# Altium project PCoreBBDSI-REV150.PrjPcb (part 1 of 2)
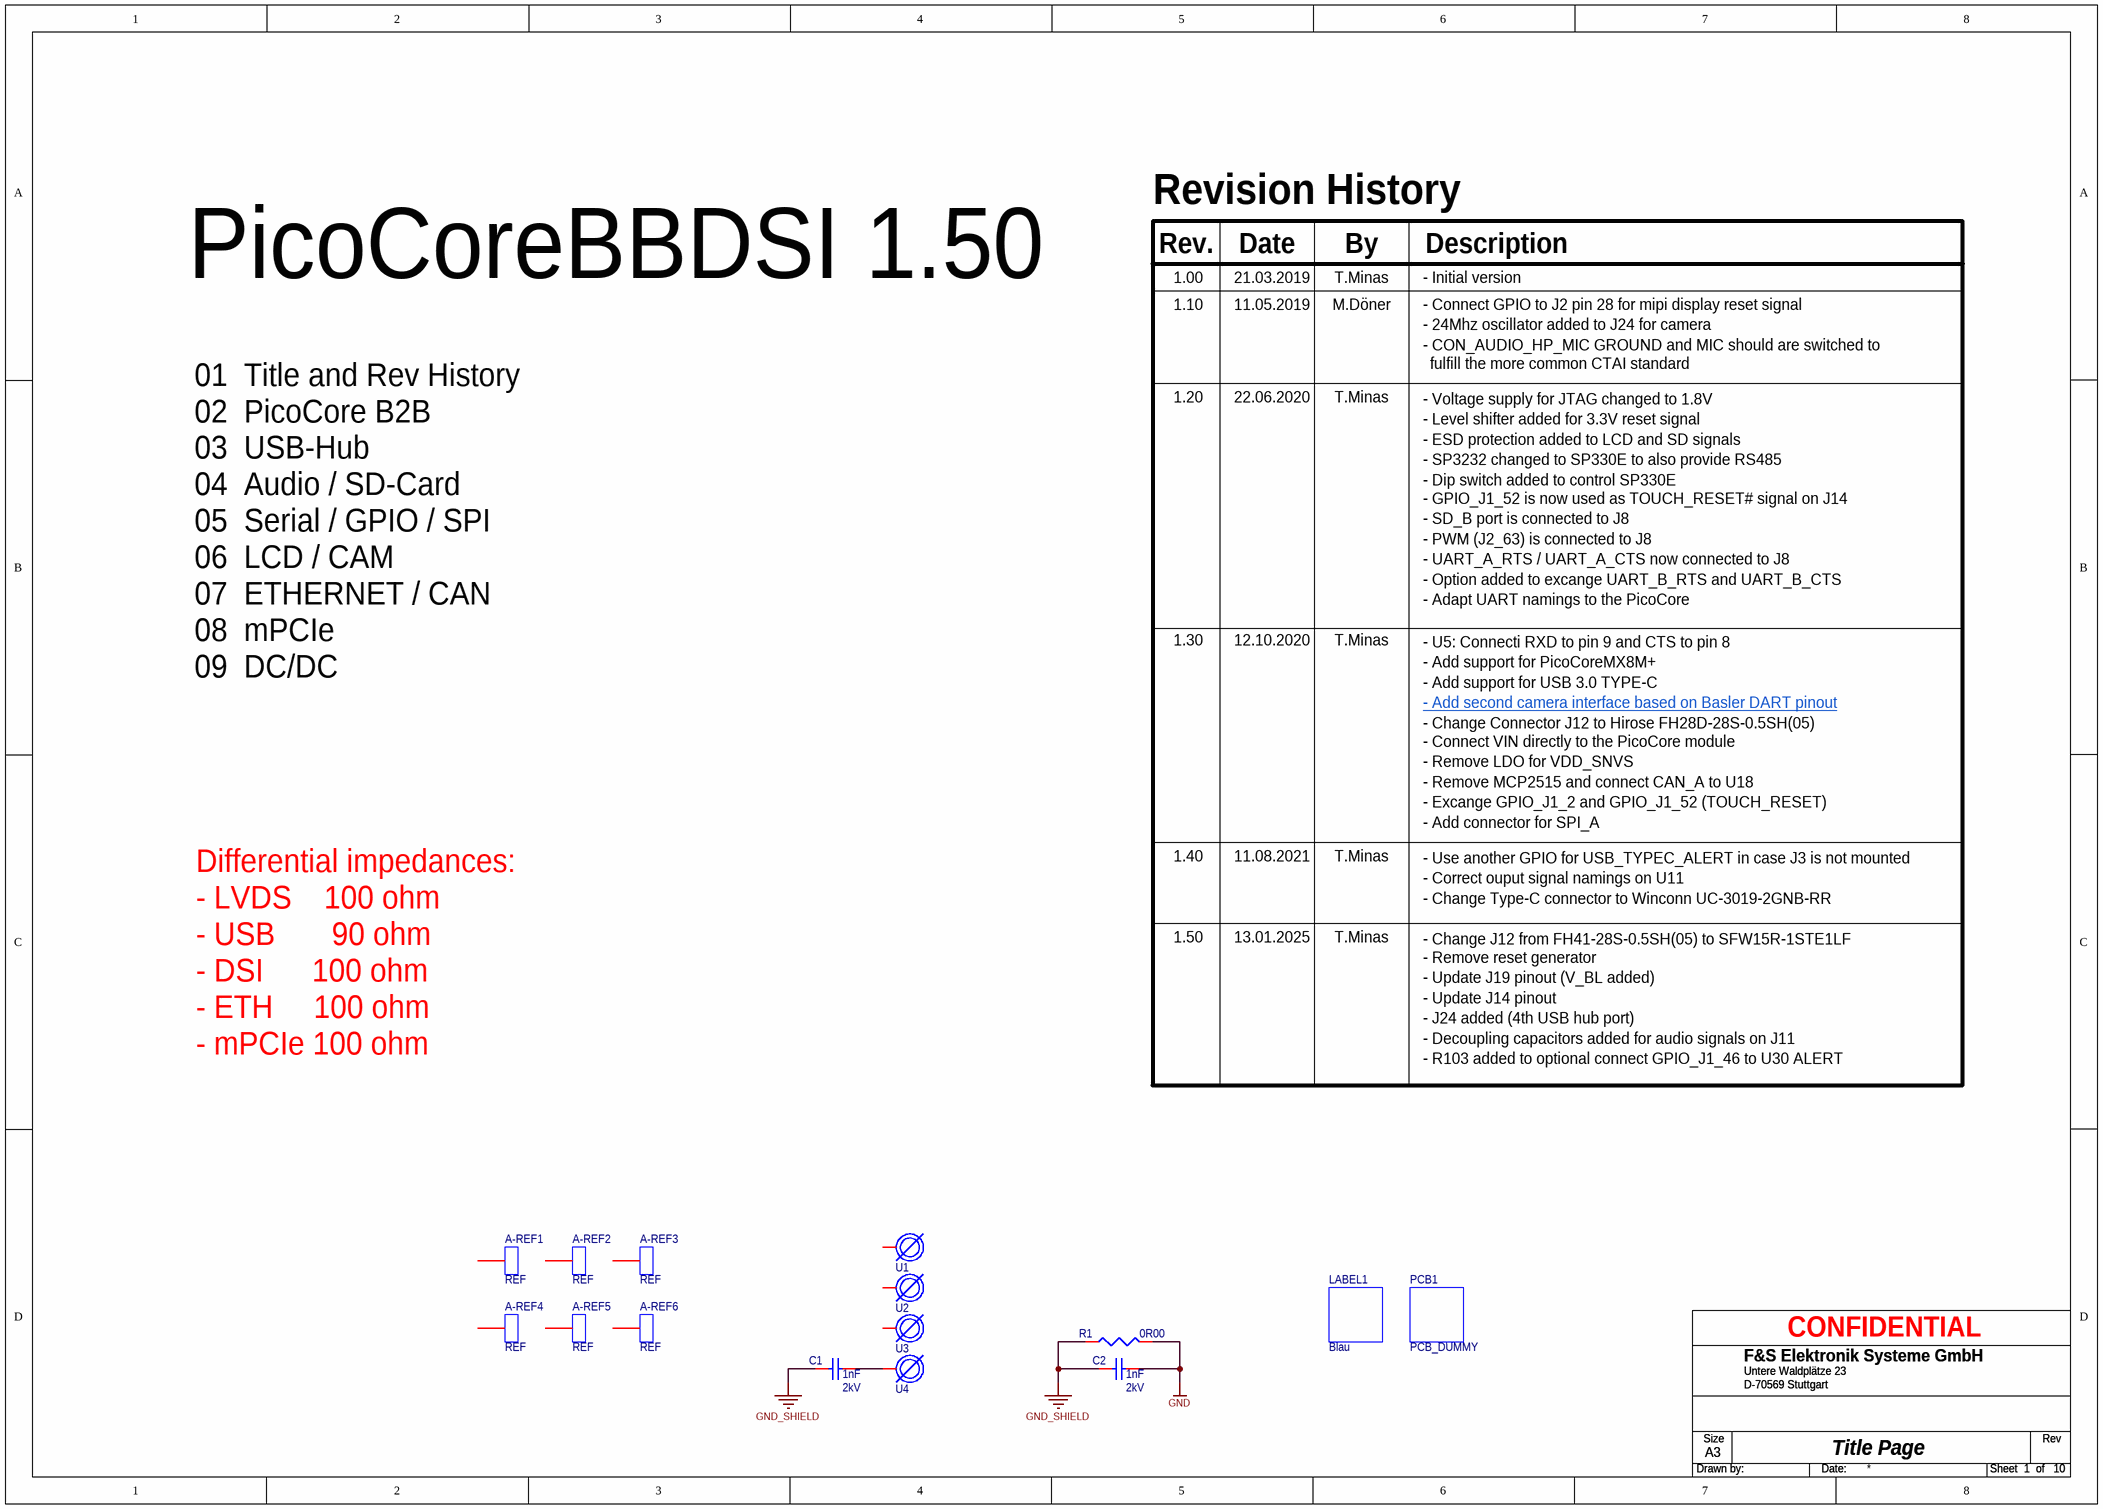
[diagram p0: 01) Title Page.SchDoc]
MA: T.Minas; projectTitle: PicoCoreBBDSI; rev: 1.50
10 sheets, 358 parts. Net scope: flat (ports and power ports of the same name join across sheets).
Board files: PCoreBBDSI-REV150.PcbDoc, PCoreBBDSI-REV150_Panel.PcbDoc
Sheets:
  01) Title Page.SchDoc
  02) PicoCore B2B.SchDoc
  03) USB-HUB.SchDoc
  04) USB AUDIO SD.SchDoc
  05) USB3.0 Type-C.SchDoc
  06) Serial GPIO.SchDoc
  07) LCD CAM.SchDoc
  08) Ethernet Can.SchDoc
  09) mPCIe.SchDoc
  10) DCDC.SchDoc

## Sheet 01) Title Page.SchDoc: Title Page
size A3; Origin: Eagle; DrawnBy: T.Minas; DocumentNumber: 1; Revision: 1.50; SheetNumber: 1; SheetTotal: 10; Project: PicoCoreBBDSI

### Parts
A-REF1  REF  [Fiducial]  (no BOM)
A-REF2  REF  [Fiducial]  (no BOM)
A-REF3  REF  [Fiducial]  (no BOM)
A-REF4  REF  [Fiducial]  (no BOM)
A-REF5  REF  [Fiducial]  (no BOM)
A-REF6  REF  [Fiducial]  (no BOM)
C1  1nF  Voltage: 2kV  [C1206]
C2  1nF  Voltage: 2kV  [C1206]
LABEL1  Blau
PCB1  PCB_DUMMY
R1  0R00  [R0805]
U1  MOUNT_HOLE  [HOLE-3.2x6]  (value not drawn)  (no BOM)
U2  MOUNT_HOLE  [HOLE-3.2x6]  (value not drawn)  (no BOM)
U3  MOUNT_HOLE  [HOLE-3.2x6]  (value not drawn)  (no BOM)
U4  MOUNT_HOLE  [HOLE-3.2x6]  (value not drawn)  (no BOM)

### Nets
GND: C2.2 R1.2
GND_SHIELD: C1.1 C2.1 R1.1
NetC1_2: C1.2 U4.1

Not connected (* = marked no-connect by the designer): A-REF1 1; A-REF2 1; A-REF3 1; A-REF4 1; A-REF5 1; A-REF6 1; U1 1; U2 1; U3 1

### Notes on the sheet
- Revision History
- Rev.
- Date
- By
- Description
- PicoCoreBBDSI 1.50
- 1.00
- 1.10
- 21.03.2019
- 11.05.2019
- T.Minas
- M.Döner
- - Initial version
- - Connect GPIO to J2 pin 28 for mipi display reset signal
- - 24Mhz oscillator added to J24 for camera
- - CON_AUDIO_HP_MIC GROUND and MIC should are switched to
- fulfill the more common CTAI standard
- 1.20
- 22.06.2020
- - Voltage supply for JTAG changed to 1.8V
- - Level shifter added for 3.3V reset signal
- - ESD protection added to LCD and SD signals
- - SP3232 changed to SP330E to also provide RS485
- - Dip switch added to control SP330E
- - GPIO_J1_52 is now used as TOUCH_RESET# signal on J14
- - SD_B port is connected to J8
- - PWM (J2_63) is connected to J8
- - UART_A_RTS / UART_A_CTS now connected to J8
- - Option added to excange UART_B_RTS and UART_B_CTS
- 1.30
- 12.10.2020
- - Adapt UART namings to the PicoCore
- - U5: Connecti RXD to pin 9 and CTS to pin 8
- 01  Title and Rev History
  02  PicoCore B2B
  03  USB-Hub
  04  Audio / SD-Card
  05  Serial / GPIO / SPI
  06  LCD / CAM
  07  ETHERNET / CAN
  08  mPCIe
  09  DC/DC
- - Add support for PicoCoreMX8M+
- - Add support for USB 3.0 TYPE-C
- - Add second camera interface based on Basler DART pinout <https://www.baslerweb.com/en/products/cameras/area-scan-cameras/dart/daa3840-30mc-s-mount/#tab=accessories>
- - Change Connector J12 to Hirose FH28D-28S-0.5SH(05)
- - Connect VIN directly to the PicoCore module
- - Remove LDO for VDD_SNVS
- - Remove MCP2515 and connect CAN_A to U18
- 1.40
- 11.08.2021
- - Excange GPIO_J1_2 and GPIO_J1_52 (TOUCH_RESET)
- - Add connector for SPI_A
- - Use another GPIO for USB_TYPEC_ALERT in case J3 is not mounted
- - Correct ouput signal namings on U11
- - Change Type-C connector to Winconn UC-3019-2GNB-RR
- 1.50
- 13.01.2025
- - Change J12 from FH41-28S-0.5SH(05) to SFW15R-1STE1LF
- - Remove reset generator
- - Update J19 pinout (V_BL added)
- - Update J14 pinout
- Differential impedances:
  - LVDS    100 ohm
  - USB       90 ohm
  - DSI      100 ohm
  - ETH     100 ohm
  - mPCIe 100 ohm
- - J24 added (4th USB hub port)
- - Decoupling capacitors added for audio signals on J11
- - R103 added to optional connect GPIO_J1_46 to U30 ALERT

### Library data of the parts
C1 C2 = 473: 1nF  10%  2kV  X7R  1206; FS-EDV-Nummer: B.CKV.89; Class: Capacitor Ceramic; Tolerance: 10; ID: 473
LABEL1 = 2752: F&S Seriennummer Label Blau; Part Number: MAC Blau; FS-EDV-Nummer: B.LAB.MACBLU; ID: 2752
PCB1 = PCB_DUMMY: FS-EDV-Nummer: B.MLP.PCBBDSI.15
R1 = 6: 0R00 0,125W max 5% SMD 0805; FS-EDV-Nummer: B.R000.2.S; Power: 0,125W; Tolerance: 5; ID: 6
U1-U4 = MOUNT_HOLE: CLASS: IC

## Sheet 02) PicoCore B2B.SchDoc: PicoCore B2B
size A3; Origin: Eagle; DrawnBy: T.Minas; DocumentNumber: 2; Revision: 1.50; SheetNumber: 2; SheetTotal: 10; Project: PicoCoreBBDSI
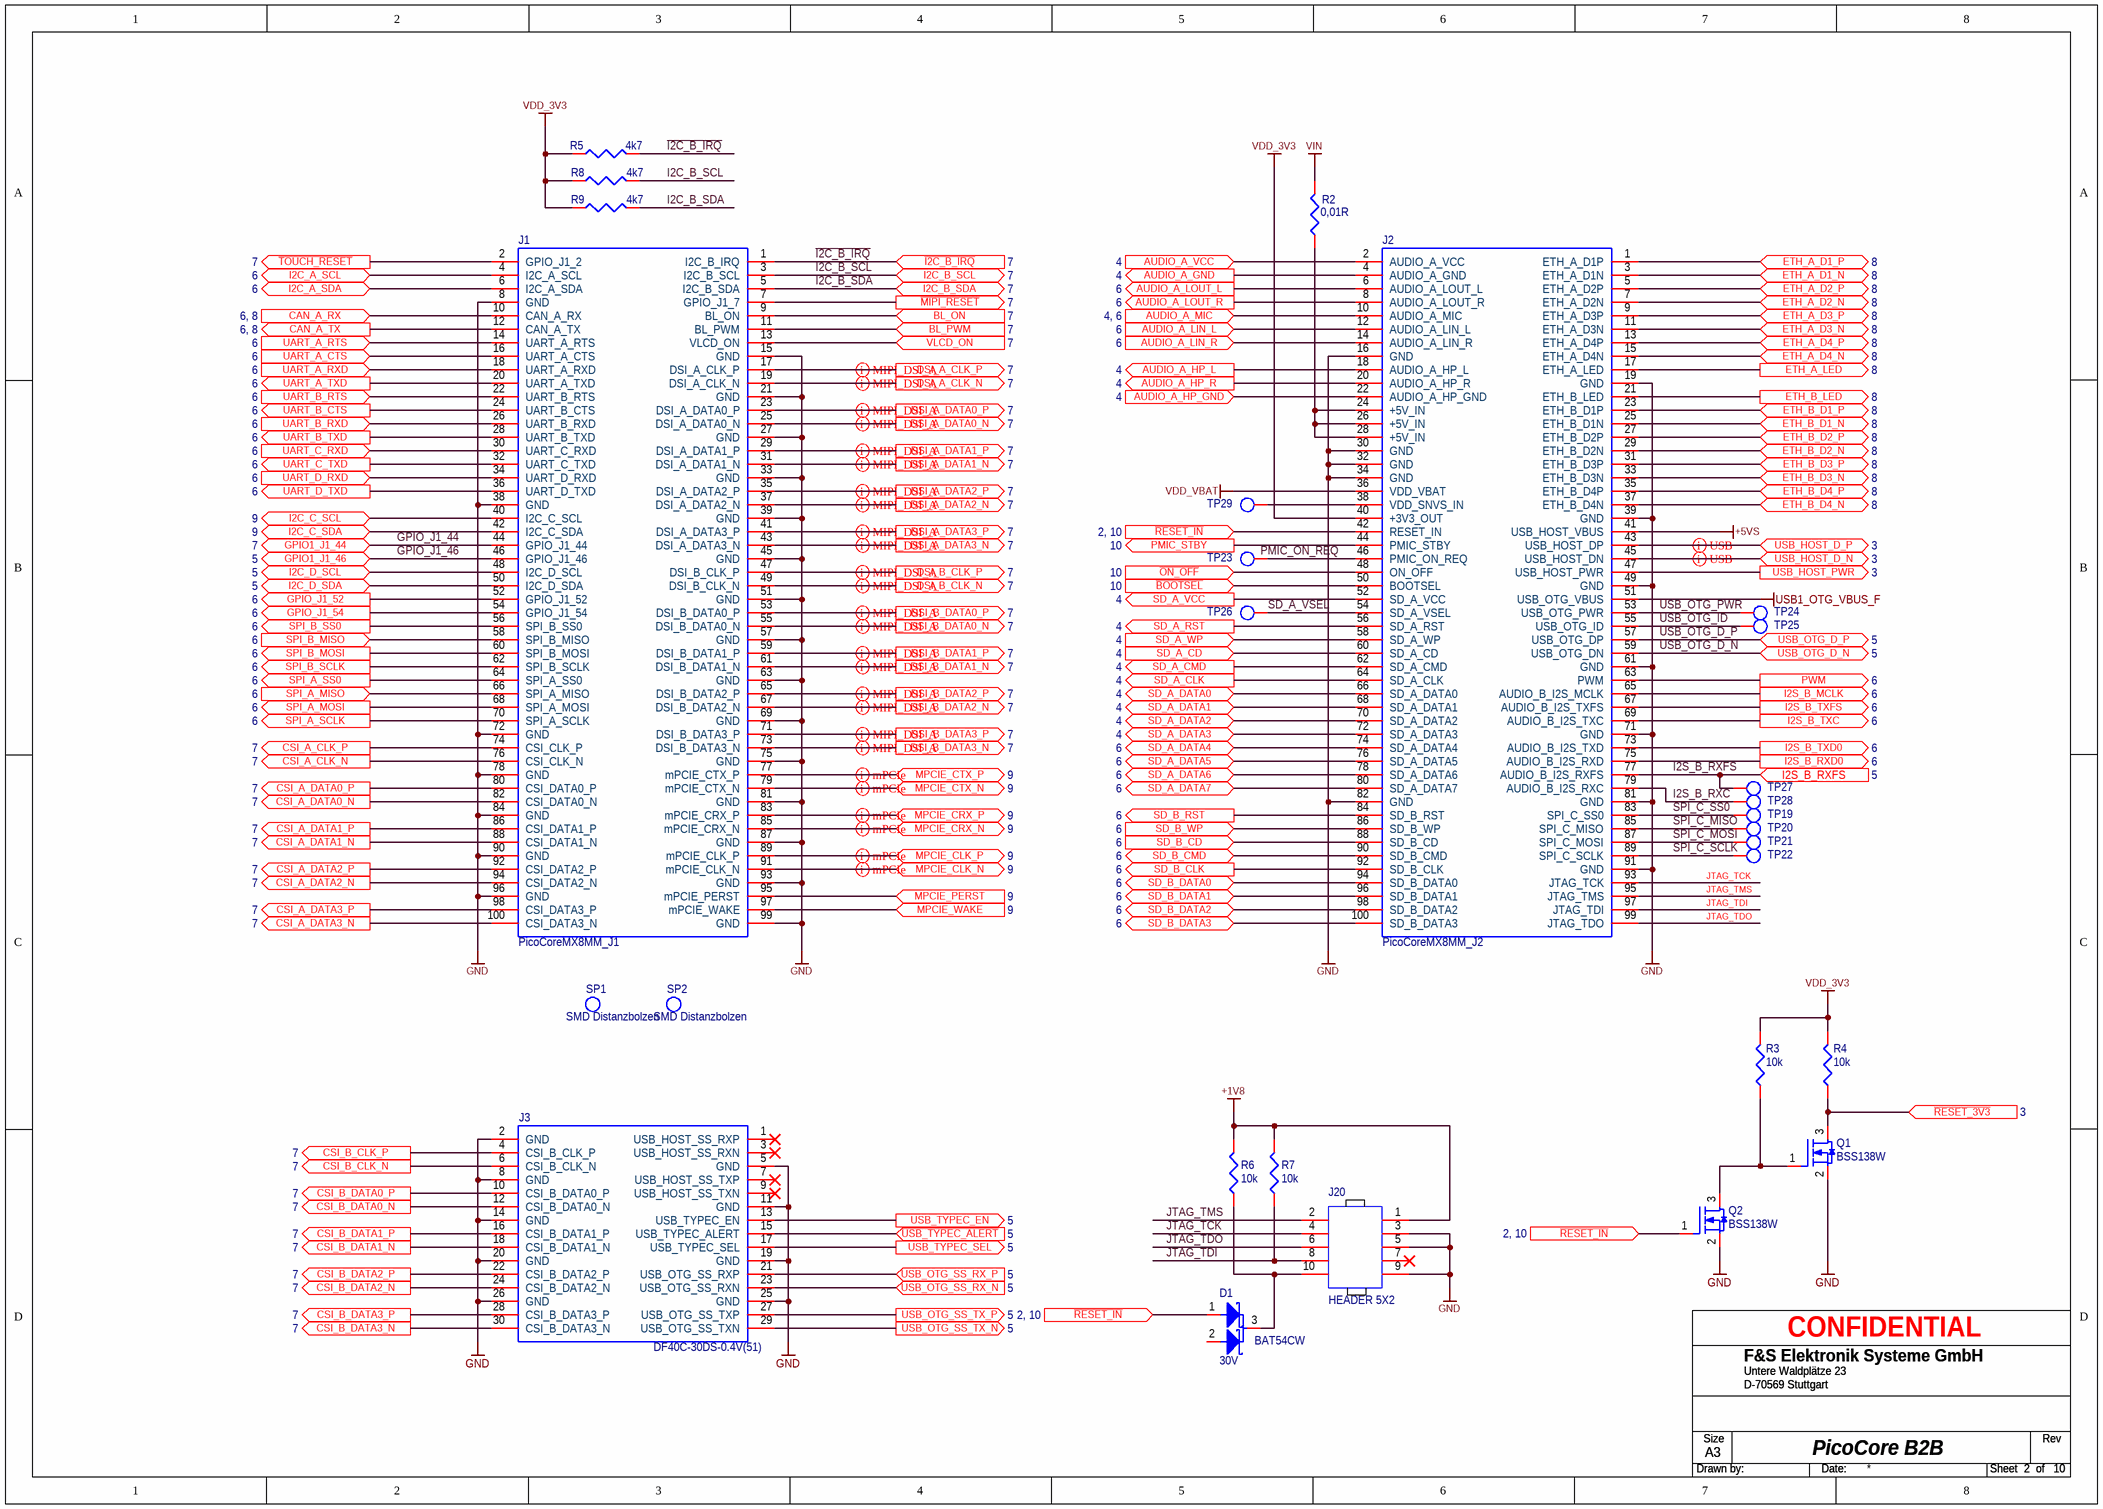
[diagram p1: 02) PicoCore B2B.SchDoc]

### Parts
D1  BAT54CW  Voltage: 30V  [SOT323 (SC70)]
J1  PicoCoreMX8MM_J1  [DF40C-100DS-0.4V(51)]
J2  PicoCoreMX8MM_J2  [DF40C-100DS-0.4V(51)]
J3  DF40C-30DS-0.4V(51)  [DF40C-30DS-0.4V(51)]
J20  HEADER 5X2  [J-B2B-5X2-127MM-WR-PHD]
Q1  BSS138W  [SOT323 (SC70)]
Q2  BSS138W  [SOT323 (SC70)]
R2  0,01R  [R0805]
R3  10k  [R0402]
R4  10k  [R0402]
R5  4k7  [R0402]
R6  10k  [R0402]
R7  10k  [R0402]
R8  4k7  [R0402]
R9  4k7  [R0402]
SP1  SMD Distanzbolzen  [Spacer_M2]
SP2  SMD Distanzbolzen  [Spacer_M2]
TP19  TESTPOINT  [TP30SR34SMD]  (value not drawn)  (no BOM)
TP20  TESTPOINT  [TP30SR34SMD]  (value not drawn)  (no BOM)
TP21  TESTPOINT  [TP30SR34SMD]  (value not drawn)  (no BOM)
TP22  TESTPOINT  [TP30SR34SMD]  (value not drawn)  (no BOM)
TP23  TESTPOINT  [TP30SR34SMD]  (value not drawn)  (no BOM)
TP24  TESTPOINT  [TP30SR34SMD]  (value not drawn)  (no BOM)
TP25  TESTPOINT  [TP30SR34SMD]  (value not drawn)  (no BOM)
TP26  TESTPOINT  [TP30SR34SMD]  (value not drawn)  (no BOM)
TP27  TESTPOINT  [TP30SR34SMD]  (value not drawn)  (no BOM)
TP28  TESTPOINT  [TP30SR34SMD]  (value not drawn)  (no BOM)
TP29  TESTPOINT  [TP30SR34SMD]  (value not drawn)  (no BOM)

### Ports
AUDIO_A_GND (out, see 4), AUDIO_A_HP_GND (in, see 4), AUDIO_A_HP_L (out, see 4), AUDIO_A_HP_R (out, see 4), AUDIO_A_LIN_L (in, see 6), AUDIO_A_LIN_R (in, see 6), AUDIO_A_LOUT_L (out, see 6), AUDIO_A_LOUT_R (out, see 6), AUDIO_A_MIC (in, see 4, 6), AUDIO_A_VCC (in, see 4), BL_ON (in, see 7), BL_PWM (in, see 7), CAN_A_RX (in, see 6, 8), CAN_A_TX (out, see 6, 8), CSI_A_CLK_N (out, see 7), CSI_A_CLK_P (out, see 7), CSI_A_DATA0_N (out, see 7), CSI_A_DATA0_P (out, see 7), CSI_A_DATA1_N (out, see 7), CSI_A_DATA1_P (out, see 7), CSI_A_DATA2_N (out, see 7), CSI_A_DATA2_P (out, see 7), CSI_A_DATA3_N (out, see 7), CSI_A_DATA3_P (out, see 7), CSI_B_CLK_N (out, see 7), CSI_B_CLK_P (out, see 7), CSI_B_DATA0_N (out, see 7), CSI_B_DATA0_P (out, see 7), CSI_B_DATA1_N (out, see 7), CSI_B_DATA1_P (out, see 7), CSI_B_DATA2_N (out, see 7), CSI_B_DATA2_P (out, see 7), CSI_B_DATA3_N (out, see 7), CSI_B_DATA3_P (out, see 7), DSI_A_CLK_N (out, see 7), DSI_A_CLK_P (out, see 7), DSI_A_DATA0_N (out, see 7), DSI_A_DATA0_P (out, see 7), DSI_A_DATA1_N (out, see 7), DSI_A_DATA1_P (out, see 7), DSI_A_DATA2_N (out, see 7), DSI_A_DATA2_P (out, see 7), DSI_A_DATA3_N (out, see 7), DSI_A_DATA3_P (out, see 7), DSI_B_CLK_N (out, see 7), DSI_B_CLK_P (out, see 7), DSI_B_DATA0_N (out, see 7), DSI_B_DATA0_P (out, see 7), DSI_B_DATA1_N (out, see 7), DSI_B_DATA1_P (out, see 7), DSI_B_DATA2_N (out, see 7), DSI_B_DATA2_P (out, see 7), DSI_B_DATA3_N (out, see 7), DSI_B_DATA3_P (out, see 7), ETH_A_D1_N (bidir, see 8), ETH_A_D1_P (bidir, see 8), ETH_A_D2_N (bidir, see 8), ETH_A_D2_P (bidir, see 8), ETH_A_D3_N (bidir, see 8), ETH_A_D3_P (bidir, see 8), ETH_A_D4_N (bidir, see 8), ETH_A_D4_P (bidir, see 8), ETH_A_LED (out, see 8), ETH_B_D1_N (bidir, see 8), ETH_B_D1_P (bidir, see 8), ETH_B_D2_N (bidir, see 8), ETH_B_D2_P (bidir, see 8), ETH_B_D3_N (bidir, see 8), ETH_B_D3_P (bidir, see 8), ETH_B_D4_N (bidir, see 8), ETH_B_D4_P (bidir, see 8), ETH_B_LED (out, see 8), GPIO1_J1_44 (bidir, see 7), GPIO1_J1_46 (bidir, see 5), GPIO_J1_52 (out, see 6), GPIO_J1_54 (out, see 6), I2C_A_SCL (bidir, see 6), I2C_A_SDA (bidir, see 6), I2C_B_SCL (bidir, see 7), I2C_B_SDA (bidir, see 7), I2C_C_SCL (bidir, see 9), I2C_C_SDA (bidir, see 9), I2C_D_SCL (bidir, see 5), I2C_D_SDA (bidir, see 5), I2S_B_MCLK (out, see 6), I2S_B_RXD0 (out, see 6), I2S_B_RXFS (in, see 5), I2S_B_TXC (out, see 6), I2S_B_TXD0 (out, see 6), I2S_B_TXFS (out, see 6), MPCIE_CLK_N (bidir, see 9), MPCIE_CLK_P (bidir, see 9), MPCIE_CRX_N (bidir, see 9), MPCIE_CRX_P (bidir, see 9), MPCIE_CTX_N (bidir, see 9), MPCIE_CTX_P (bidir, see 9), MPCIE_PERST (in, see 9), MPCIE_WAKE (in, see 9), PMIC_STBY (out, see 10), PWM (out, see 6), SD_A_CD (in, see 4), SD_A_CLK (out, see 4), SD_A_CMD (out, see 4), SD_A_DATA0 (bidir, see 4), SD_A_DATA1 (bidir, see 4), SD_A_DATA2 (bidir, see 4), SD_A_DATA3 (bidir, see 4), SD_A_DATA4 (bidir, see 6), SD_A_DATA5 (bidir, see 6), SD_A_DATA6 (bidir, see 6), SD_A_DATA7 (bidir, see 6), SD_A_RST (out, see 4), SD_A_VCC (out, see 4), SD_A_WP (in, see 4), SD_B_CD (in, see 6), SD_B_CLK (out, see 6), SD_B_CMD (bidir, see 6), SD_B_DATA0 (bidir, see 6), SD_B_DATA1 (bidir, see 6), SD_B_DATA2 (bidir, see 6), SD_B_DATA3 (bidir, see 6), SD_B_RST (out, see 6), SD_B_WP (in, see 6), SPI_A_MISO (in, see 6), SPI_A_MOSI (out, see 6), SPI_A_SCLK (out, see 6), SPI_A_SS0 (out, see 6), SPI_B_MISO (in, see 6), SPI_B_MOSI (out, see 6), SPI_B_SCLK (out, see 6), SPI_B_SS0 (out, see 6), UART_A_CTS (in, see 6), UART_A_RTS (in, see 6), UART_A_RXD (in, see 6), UART_A_TXD (out, see 6), UART_B_CTS (out, see 6), UART_B_RTS (in, see 6), UART_B_RXD (in, see 6), UART_B_TXD (out, see 6), UART_C_RXD (in, see 6), UART_C_TXD (out, see 6), UART_D_RXD (in, see 6), UART_D_TXD (out, see 6), USB_HOST_D_N (bidir, see 3), USB_HOST_D_P (bidir, see 3), USB_HOST_PWR (out, see 3), USB_OTG_D_N (bidir, see 5), USB_OTG_D_P (bidir, see 5), USB_OTG_SS_RX_N (in, see 5), USB_OTG_SS_RX_P (in, see 5), USB_OTG_SS_TX_N (out, see 5), USB_OTG_SS_TX_P (out, see 5), USB_TYPEC_EN (out, see 5), USB_TYPEC_SEL (out, see 5), VLCD_ON (in, see 7), ~{BOOTSEL} (in, see 10), ~{I2C_B_IRQ} (in, see 7), ~{MIPI_RESET} (out, see 7), ~{ON_OFF} (in, see 10), ~{RESET_3V3} (in, see 3), ~{RESET_IN} (in, see 2, 10), ~{TOUCH_RESET} (out, see 7), ~{USB_TYPEC_ALERT} (in, see 5)

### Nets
+1V8: J20.1 R6.2 R7.2
+5VS: J2.41(USB_HOST_VBUS)
GND: J1.8(GND) J1.15(GND) J1.21(GND) J1.27(GND) J1.33(GND) J1.38(GND) J1.39(GND) J1.45(GND) J1.51(GND) J1.57(GND) J1.63(GND) J1.69(GND) J1.72(GND) J1.75(GND) J1.78(GND) J1.81(GND) J1.84(GND) J1.87(GND) J1.90(GND) J1.93(GND) J1.96(GND) J1.99(GND) J2.16(GND) J2.19(GND) J2.30(GND) J2.32(GND) J2.34(GND) J2.39(GND) J2.49(GND) J2.61(GND) J2.71(GND) J2.81(GND) J2.82(GND) J2.91(GND) J3.2(GND) J3.5(GND) J3.8(GND) J3.11(GND) J3.14(GND) J3.19(GND) J3.20(GND) J3.25(GND) J3.26(GND) J20.3 J20.5 J20.9 Q1.2 Q2.2
USB1_OTG_VBUS_F: J2.51(USB_OTG_VBUS)
VDD_3V3: J2.40(+3V3_OUT) R3.2 R4.2 R5.1 R8.1 R9.1
VDD_VBAT: J2.36(VDD_VBAT)
VIN: R2.2
~{USB_OTG_ID}: J2.55(USB_OTG_ID) TP25.1(TP)
~{USB_OTG_PWR}: J2.53(USB_OTG_PWR) TP24.1(TP)
AUDIO_A_GND: J2.4(AUDIO_A_GND) ; port AUDIO_A_GND
CSI_A_CLK_N: J1.76(CSI_CLK_N) ; port CSI_A_CLK_N
CSI_A_CLK_P: J1.74(CSI_CLK_P) ; port CSI_A_CLK_P
CSI_A_DATA0_N: J1.82(CSI_DATA0_N) ; port CSI_A_DATA0_N
CSI_A_DATA0_P: J1.80(CSI_DATA0_P) ; port CSI_A_DATA0_P
CSI_A_DATA1_N: J1.88(CSI_DATA1_N) ; port CSI_A_DATA1_N
CSI_A_DATA1_P: J1.86(CSI_DATA1_P) ; port CSI_A_DATA1_P
CSI_B_CLK_N: J3.6(CSI_B_CLK_N) ; port CSI_B_CLK_N
CSI_B_CLK_P: J3.4(CSI_B_CLK_P) ; port CSI_B_CLK_P
CSI_B_DATA0_N: J3.12(CSI_B_DATA0_N) ; port CSI_B_DATA0_N
CSI_B_DATA0_P: J3.10(CSI_B_DATA0_P) ; port CSI_B_DATA0_P
CSI_B_DATA1_N: J3.18(CSI_B_DATA1_N) ; port CSI_B_DATA1_N
CSI_B_DATA1_P: J3.16(CSI_B_DATA1_P) ; port CSI_B_DATA1_P
CSI_B_DATA2_N: J3.24(CSI_B_DATA2_N) ; port CSI_B_DATA2_N
CSI_B_DATA2_P: J3.22(CSI_B_DATA2_P) ; port CSI_B_DATA2_P
CSI_B_DATA3_N: J3.30(CSI_B_DATA3_N) ; port CSI_B_DATA3_N
CSI_B_DATA3_P: J3.28(CSI_B_DATA3_P) ; port CSI_B_DATA3_P
DSI_A_CLK_N: J1.19(DSI_A_CLK_N) ; port DSI_A_CLK_N
DSI_A_CLK_P: J1.17(DSI_A_CLK_P) ; port DSI_A_CLK_P
DSI_A_DATA0_N: J1.25(DSI_A_DATA0_N) ; port DSI_A_DATA0_N
DSI_A_DATA0_P: J1.23(DSI_A_DATA0_P) ; port DSI_A_DATA0_P
DSI_A_DATA1_N: J1.31(DSI_A_DATA1_N) ; port DSI_A_DATA1_N
DSI_A_DATA1_P: J1.29(DSI_A_DATA1_P) ; port DSI_A_DATA1_P
DSI_A_DATA2_N: J1.37(DSI_A_DATA2_N) ; port DSI_A_DATA2_N
DSI_A_DATA2_P: J1.35(DSI_A_DATA2_P) ; port DSI_A_DATA2_P
DSI_A_DATA3_N: J1.43(DSI_A_DATA3_N) ; port DSI_A_DATA3_N
DSI_A_DATA3_P: J1.41(DSI_A_DATA3_P) ; port DSI_A_DATA3_P
DSI_B_CLK_N: J1.49(DSI_B_CLK_N) ; port DSI_B_CLK_N
DSI_B_CLK_P: J1.47(DSI_B_CLK_P) ; port DSI_B_CLK_P
DSI_B_DATA0_N: J1.55(DSI_B_DATA0_N) ; port DSI_B_DATA0_N
DSI_B_DATA0_P: J1.53(DSI_B_DATA0_P) ; port DSI_B_DATA0_P
DSI_B_DATA1_N: J1.61(DSI_B_DATA1_N) ; port DSI_B_DATA1_N
DSI_B_DATA1_P: J1.59(DSI_B_DATA1_P) ; port DSI_B_DATA1_P
DSI_B_DATA2_N: J1.67(DSI_B_DATA2_N) ; port DSI_B_DATA2_N
DSI_B_DATA2_P: J1.65(DSI_B_DATA2_P) ; port DSI_B_DATA2_P
DSI_B_DATA3_N: J1.73(DSI_B_DATA3_N) ; port DSI_B_DATA3_N
DSI_B_DATA3_P: J1.71(DSI_B_DATA3_P) ; port DSI_B_DATA3_P
ETH_A_D1_N: J2.3(ETH_A_D1N) ; port ETH_A_D1_N
ETH_A_D1_P: J2.1(ETH_A_D1P) ; port ETH_A_D1_P
ETH_A_D2_N: J2.7(ETH_A_D2N) ; port ETH_A_D2_N
ETH_A_D2_P: J2.5(ETH_A_D2P) ; port ETH_A_D2_P
ETH_A_D3_N: J2.11(ETH_A_D3N) ; port ETH_A_D3_N
ETH_A_D3_P: J2.9(ETH_A_D3P) ; port ETH_A_D3_P
ETH_A_D4_N: J2.15(ETH_A_D4N) ; port ETH_A_D4_N
ETH_A_D4_P: J2.13(ETH_A_D4P) ; port ETH_A_D4_P
ETH_B_D1_N: J2.25(ETH_B_D1N) ; port ETH_B_D1_N
ETH_B_D1_P: J2.23(ETH_B_D1P) ; port ETH_B_D1_P
ETH_B_D2_N: J2.29(ETH_B_D2N) ; port ETH_B_D2_N
ETH_B_D2_P: J2.27(ETH_B_D2P) ; port ETH_B_D2_P
ETH_B_D3_N: J2.33(ETH_B_D3N) ; port ETH_B_D3_N
ETH_B_D3_P: J2.31(ETH_B_D3P) ; port ETH_B_D3_P
ETH_B_D4_N: J2.37(ETH_B_D4N) ; port ETH_B_D4_N
ETH_B_D4_P: J2.35(ETH_B_D4P) ; port ETH_B_D4_P
GPIO_J1_44: J1.44(GPIO_J1_44) ; port GPIO1_J1_44
GPIO_J1_46: J1.46(GPIO_J1_46) ; port GPIO1_J1_46
I2C_B_SCL: J1.3(I2C_B_SCL) R8.2 ; port I2C_B_SCL
I2C_B_SDA: J1.5(I2C_B_SDA) R9.2 ; port I2C_B_SDA
I2S_B_RXC: J2.79(AUDIO_B_I2S_RXC) TP28.1(TP)
I2S_B_RXFS: J2.77(AUDIO_B_I2S_RXFS) TP27.1(TP) ; port I2S_B_RXFS
~{I2C_B_IRQ}: J1.1(I2C_B_IRQ) R5.2 ; port ~{I2C_B_IRQ}
JTAG_TCK: J2.93(JTAG_TCK) J20.4
JTAG_TDI: J2.97(JTAG_TDI) J20.8 R7.1
JTAG_TDO: J2.99(JTAG_TDO) J20.6
JTAG_TMS: J2.95(JTAG_TMS) J20.2
MPCIE_CLK_N: J1.91(mPCIE_CLK_N) ; port MPCIE_CLK_N
MPCIE_CLK_P: J1.89(mPCIE_CLK_P) ; port MPCIE_CLK_P
MPCIE_CRX_N: J1.85(mPCIE_CRX_N) ; port MPCIE_CRX_N
MPCIE_CRX_P: J1.83(mPCIE_CRX_P) ; port MPCIE_CRX_P
MPCIE_CTX_N: J1.79(mPCIE_CTX_N) ; port MPCIE_CTX_N
MPCIE_CTX_P: J1.77(mPCIE_CTX_P) ; port MPCIE_CTX_P
SD_A_VSEL: J2.54(SD_A_VSEL) TP26.1(TP)
SPI_C_MISO: J2.85(SPI_C_MISO) TP20.1(TP)
SPI_C_MOSI: J2.87(SPI_C_MOSI) TP21.1(TP)
SPI_C_SCLK: J2.89(SPI_C_SCLK) TP22.1(TP)
SPI_C_SS0: J2.83(SPI_C_SS0) TP19.1(TP)
USB1_RX_N: J3.23(USB_OTG_SS_RXN) ; port USB_OTG_SS_RX_N
USB1_RX_P: J3.21(USB_OTG_SS_RXP) ; port USB_OTG_SS_RX_P
USB1_TX_N: J3.29(USB_OTG_SS_TXN) ; port USB_OTG_SS_TX_N
USB1_TX_P: J3.27(USB_OTG_SS_TXP) ; port USB_OTG_SS_TX_P
USB_OTG_D_N: J2.59(USB_OTG_DN) ; port USB_OTG_D_N
USB_OTG_D_P: J2.57(USB_OTG_DP) ; port USB_OTG_D_P
USBD_N: J2.45(USB_HOST_DN) ; port USB_HOST_D_N
USBD_P: J2.43(USB_HOST_DP) ; port USB_HOST_D_P
NetC20_2: J2.64(SD_A_CLK) ; port SD_A_CLK
NetC26_1: J2.18(AUDIO_A_HP_L) ; port AUDIO_A_HP_L
NetC27_1: J2.20(AUDIO_A_HP_R) ; port AUDIO_A_HP_R
NetC29_2: J2.10(AUDIO_A_MIC) ; port AUDIO_A_MIC
NetC30_2: J2.2(AUDIO_A_VCC) ; port AUDIO_A_VCC
NetC48_2: J2.14(AUDIO_A_LIN_R) ; port AUDIO_A_LIN_R
NetC51_1: J2.8(AUDIO_A_LOUT_R) ; port AUDIO_A_LOUT_R
NetC52_2: J2.12(AUDIO_A_LIN_L) ; port AUDIO_A_LIN_L
NetC67_1: J2.6(AUDIO_A_LOUT_L) ; port AUDIO_A_LOUT_L
NetD1_1: D1.1(ANODE1) J2.42(RESET_IN) Q2.1 ; port ~{RESET_IN}
NetD1_3: D1.3(CATHODE) J20.10 R6.1
NetD3_3: J2.56(SD_A_RST) ; port SD_A_RST
NetJ1_2: J1.2(GPIO_J1_2) ; port ~{TOUCH_RESET}
NetJ1_4: J1.4(I2C_A_SCL) ; port I2C_A_SCL
NetJ1_6: J1.6(I2C_A_SDA) ; port I2C_A_SDA
NetJ1_7: J1.7(GPIO_J1_7) ; port ~{MIPI_RESET}
NetJ1_9: J1.9(BL_ON) ; port BL_ON
NetJ1_10: J1.10(CAN_A_RX) ; port CAN_A_RX
NetJ1_11: J1.11(BL_PWM) ; port BL_PWM
NetJ1_12: J1.12(CAN_A_TX) ; port CAN_A_TX
NetJ1_13: J1.13(VLCD_ON) ; port VLCD_ON
NetJ1_14: J1.14(UART_A_RTS) ; port UART_A_RTS
NetJ1_16: J1.16(UART_A_CTS) ; port UART_A_CTS
NetJ1_18: J1.18(UART_A_RXD) ; port UART_A_RXD
NetJ1_20: J1.20(UART_A_TXD) ; port UART_A_TXD
NetJ1_22: J1.22(UART_B_RTS) ; port UART_B_RTS
NetJ1_24: J1.24(UART_B_CTS) ; port UART_B_CTS
NetJ1_26: J1.26(UART_B_RXD) ; port UART_B_RXD
NetJ1_28: J1.28(UART_B_TXD) ; port UART_B_TXD
NetJ1_30: J1.30(UART_C_RXD) ; port UART_C_RXD
NetJ1_32: J1.32(UART_C_TXD) ; port UART_C_TXD
NetJ1_34: J1.34(UART_D_RXD) ; port UART_D_RXD
NetJ1_36: J1.36(UART_D_TXD) ; port UART_D_TXD
NetJ1_40: J1.40(I2C_C_SCL) ; port I2C_C_SCL
NetJ1_42: J1.42(I2C_C_SDA) ; port I2C_C_SDA
NetJ1_48: J1.48(I2C_D_SCL) ; port I2C_D_SCL
NetJ1_50: J1.50(I2C_D_SDA) ; port I2C_D_SDA
NetJ1_52: J1.52(GPIO_J1_52) ; port GPIO_J1_52
NetJ1_54: J1.54(GPIO_J1_54) ; port GPIO_J1_54
NetJ1_56: J1.56(SPI_B_SS0) ; port SPI_B_SS0
NetJ1_58: J1.58(SPI_B_MISO) ; port SPI_B_MISO
NetJ1_60: J1.60(SPI_B_MOSI) ; port SPI_B_MOSI
NetJ1_62: J1.62(SPI_B_SCLK) ; port SPI_B_SCLK
NetJ1_64: J1.64(SPI_A_SS0) ; port SPI_A_SS0
NetJ1_66: J1.66(SPI_A_MISO) ; port SPI_A_MISO
NetJ1_68: J1.68(SPI_A_MOSI) ; port SPI_A_MOSI
NetJ1_70: J1.70(SPI_A_SCLK) ; port SPI_A_SCLK
NetJ1_92: J1.92(CSI_DATA2_P) ; port CSI_A_DATA2_P
NetJ1_94: J1.94(CSI_DATA2_N) ; port CSI_A_DATA2_N
NetJ1_95: J1.95(mPCIE_PERST) ; port MPCIE_PERST
NetJ1_97: J1.97(mPCIE_WAKE) ; port MPCIE_WAKE
NetJ1_98: J1.98(CSI_DATA3_P) ; port CSI_A_DATA3_P
NetJ1_100: J1.100(CSI_DATA3_N) ; port CSI_A_DATA3_N
NetJ2_17: J2.17(ETH_A_LED) ; port ETH_A_LED
NetJ2_21: J2.21(ETH_B_LED) ; port ETH_B_LED
NetJ2_22: J2.22(AUDIO_A_HP_GND) ; port AUDIO_A_HP_GND
NetJ2_24: J2.24(+5V_IN) J2.26(+5V_IN) J2.28(+5V_IN) R2.1
NetJ2_38: J2.38(VDD_SNVS_IN) TP29.1(TP)
NetJ2_44: J2.44(PMIC_STBY) ; port PMIC_STBY
NetJ2_46: J2.46(PMIC_ON_REQ) TP23.1(TP)
NetJ2_47: J2.47(USB_HOST_PWR) ; port USB_HOST_PWR
NetJ2_48: J2.48(ON_OFF) ; port ~{ON_OFF}
NetJ2_50: J2.50(BOOTSEL) ; port ~{BOOTSEL}
NetJ2_52: J2.52(SD_A_VCC) ; port SD_A_VCC
NetJ2_58: J2.58(SD_A_WP) ; port SD_A_WP
NetJ2_60: J2.60(SD_A_CD) ; port SD_A_CD
NetJ2_62: J2.62(SD_A_CMD) ; port SD_A_CMD
NetJ2_63: J2.63(PWM) ; port PWM
NetJ2_65: J2.65(AUDIO_B_I2S_MCLK) ; port I2S_B_MCLK
NetJ2_66: J2.66(SD_A_DATA0) ; port SD_A_DATA0
NetJ2_67: J2.67(AUDIO_B_I2S_TXFS) ; port I2S_B_TXFS
NetJ2_68: J2.68(SD_A_DATA1) ; port SD_A_DATA1
NetJ2_69: J2.69(AUDIO_B_I2S_TXC) ; port I2S_B_TXC
NetJ2_70: J2.70(SD_A_DATA2) ; port SD_A_DATA2
NetJ2_72: J2.72(SD_A_DATA3) ; port SD_A_DATA3
NetJ2_73: J2.73(AUDIO_B_I2S_TXD) ; port I2S_B_TXD0
NetJ2_74: J2.74(SD_A_DATA4) ; port SD_A_DATA4
NetJ2_75: J2.75(AUDIO_B_I2S_RXD) ; port I2S_B_RXD0
NetJ2_76: J2.76(SD_A_DATA5) ; port SD_A_DATA5
NetJ2_78: J2.78(SD_A_DATA6) ; port SD_A_DATA6
NetJ2_80: J2.80(SD_A_DATA7) ; port SD_A_DATA7
NetJ2_84: J2.84(SD_B_RST) ; port SD_B_RST
NetJ2_86: J2.86(SD_B_WP) ; port SD_B_WP
NetJ2_88: J2.88(SD_B_CD) ; port SD_B_CD
NetJ2_90: J2.90(SD_B_CMD) ; port SD_B_CMD
NetJ2_92: J2.92(SD_B_CLK) ; port SD_B_CLK
NetJ2_94: J2.94(SD_B_DATA0) ; port SD_B_DATA0
NetJ2_96: J2.96(SD_B_DATA1) ; port SD_B_DATA1
NetJ2_98: J2.98(SD_B_DATA2) ; port SD_B_DATA2
NetJ2_100: J2.100(SD_B_DATA3) ; port SD_B_DATA3
NetJ3_13: J3.13(USB_TYPEC_EN) ; port USB_TYPEC_EN
NetJ3_15: J3.15(USB_TYPEC_ALERT) ; port ~{USB_TYPEC_ALERT}
NetJ3_17: J3.17(USB_TYPEC_SEL) ; port USB_TYPEC_SEL
NetQ1_1: Q1.1 Q2.3 R3.1
NetQ1_3: Q1.3 R4.1 ; port ~{RESET_3V3}

Not connected (* = marked no-connect by the designer): D1 2(ANODE2); J3 1(USB_HOST_SS_RXP)* 3(USB_HOST_SS_RXN)* 7(USB_HOST_SS_TXP)* 9(USB_HOST_SS_TXN)*; J20 7*

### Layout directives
differential pair; differential pair class mPCIe: MPCIE_CLK_N, MPCIE_CLK_P, MPCIE_CRX_N, MPCIE_CRX_P, MPCIE_CTX_N, MPCIE_CTX_P
differential pair; differential pair class MIPI-DSI_A: DSI_A_CLK_N, DSI_A_CLK_P, DSI_A_DATA0_N, DSI_A_DATA0_P, DSI_A_DATA1_N, DSI_A_DATA1_P, DSI_A_DATA2_N, DSI_A_DATA2_P, DSI_A_DATA3_N, DSI_A_DATA3_P, DSI_B_CLK_N, DSI_B_CLK_P, DSI_B_DATA0_N, DSI_B_DATA0_P, DSI_B_DATA1_N, DSI_B_DATA1_P, DSI_B_DATA2_N, DSI_B_DATA2_P, DSI_B_DATA3_N, DSI_B_DATA3_P
differential pair; differential pair class USB: USBD_N, USBD_P

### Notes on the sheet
- Labels drawn without touching a wire or pin: PMIC_ON_REQ

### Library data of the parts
D1 = 2695: BAT54CW  30V  200mA  Dual Common Cathode SOT-323; FS-EDV-Nummer: B.DSCHOT.5; Class: DIOD; ID: 2695
J1 = PicoCoreMX8MM_J1: FS-EDV-Nummer: B.MBU.2R100PS.3
J2 = PicoCoreMX8MM_J2: FS-EDV-Nummer: B.MBU.2R100PS.3
J3 = 2764: 30 pol. 2 reih. Steckerl. SMD RM0,4; ID: 2764; Class: Connector; FS-EDV-Nummer: B.MBU.2R30PS.1
J20 = 2706: Stiftl. 10 pol. 2 reih. SMD RM:1,27; Part Number: M50-3610542; FS-EDV-Nummer: B.MST.2R10PS.14; Class: Connector; ID: 2706
Q1 Q2 = 2689: BSS138W SOT323(SC-70) N-Kanal; FS-EDV-Nummer: B.TPMFN.10; Class: MOSFET; ID: 2689
R2 = 187: 0,01R 1/4W max 5% SMD 0805; FS-EDV-Nummer: B.R0R01.1; Tolerance: 5; ID: 187
R3 R4 R6 R7 = 170: 10k 1/16W 1% SMD 0402; FS-EDV-Nummer: B.R10K.3; Tolerance: 1; ID: 170
R5 R8 R9 = 184: 4k7 1/16W max 5% SMD 0402; FS-EDV-Nummer: B.R4K7.3; Tolerance: 5; ID: 184
SP1 SP2 = 2747: SMD-Distanzbolzen 1.5mm M2; Part Number: 9774015243R; ID: 2747; Class: Mechanical; FS-EDV-Nummer: B.MSCHR.22

## Sheet 03) USB-HUB.SchDoc: USB-Hub
size A3; DrawnBy: T.Minas; DocumentNumber: 3; Revision: 1.50; SheetNumber: 3; SheetTotal: 10; Project: PicoCoreBBDSI
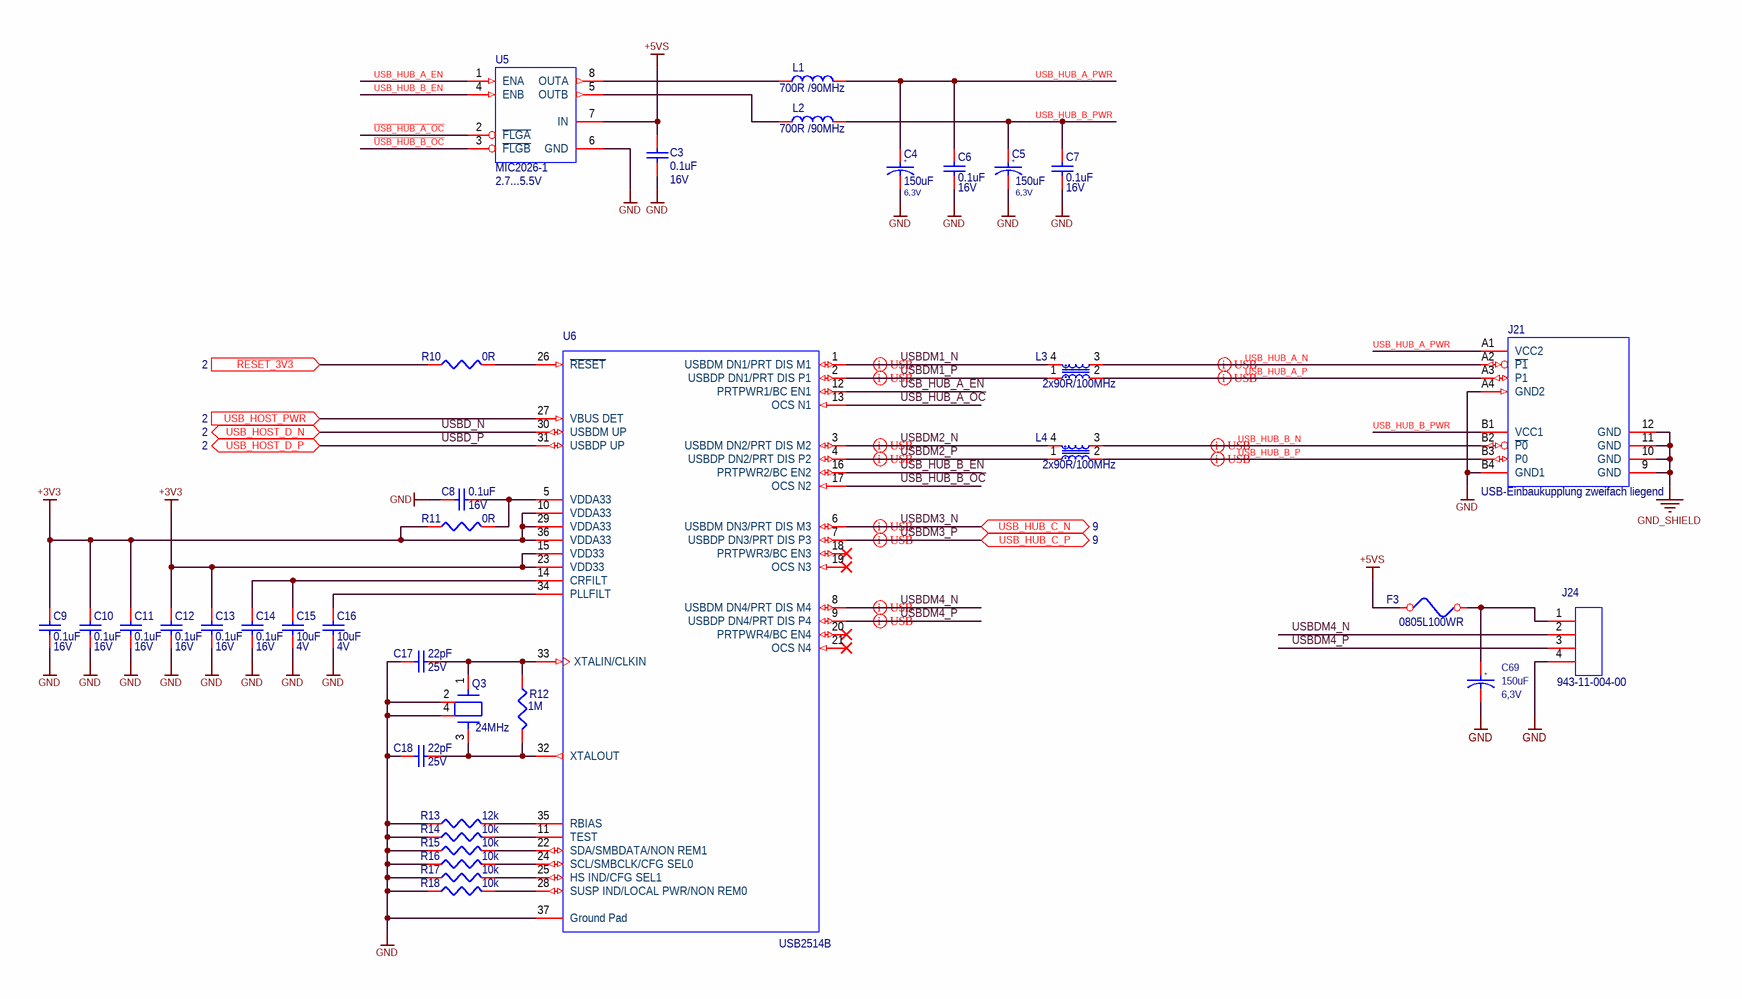
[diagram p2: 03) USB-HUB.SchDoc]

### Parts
C3  0.1uF  Voltage: 16V  [C0402]
C4  150uF  Voltage: 6,3V  [CAPMP3528X21N]
C5  150uF  Voltage: 6,3V  [CAPMP3528X21N]
C6  0.1uF  Voltage: 16V  [C0402]
C7  0.1uF  Voltage: 16V  [C0402]
C8  0.1uF  Voltage: 16V  [C0402]
C9  0.1uF  Voltage: 16V  [C0402]
C10  0.1uF  Voltage: 16V  [C0402]
C11  0.1uF  Voltage: 16V  [C0402]
C12  0.1uF  Voltage: 16V  [C0402]
C13  0.1uF  Voltage: 16V  [C0402]
C14  0.1uF  Voltage: 16V  [C0402]
C15  10uF  Voltage: 4V  [C0402]
C16  10uF  Voltage: 4V  [C0402]
C17  22pF  Voltage: 25V  [C0402]
C18  22pF  Voltage: 25V  [C0402]
C69  150uF  Voltage: 6,3V  [CAPMP3528X21N]
F3  0805L100WR  [FUSE0805]
J21  USB-Einbaukupplung zweifach liegend  [LUMBERG-2410-03]
J24  943-11-004-00  [B4B-XH-A]
L1  700R /90MHz  [L1206]
L2  700R /90MHz  [L1206]
L3  2x90R/100MHz  [USBSHOCK4-0805-12]
L4  2x90R/100MHz  [USBSHOCK4-0805-12]
Q3  24MHz  [XTALD-4-302X205M]
R10  0R  [R0402]
R11  0R  [R0402]
R12  1M  [R0402]
R13  12k  [R0402]
R14  10k  [R0402]
R15  10k  [R0402]
R16  10k  [R0402]
R17  10k  [R0402]
R18  10k  [R0402]
U5  MIC2026-1  Voltage: 2.7...5.5V  [MIC2026]
U6  USB2514B  [USB2514]

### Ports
USB_HOST_D_N (bidir, see 2), USB_HOST_D_P (bidir, see 2), USB_HOST_PWR (in, see 2), USB_HUB_C_N (bidir, see 9), USB_HUB_C_P (bidir, see 9), ~{RESET_3V3} (in, see 2)

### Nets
+3V3: C9.2 C10.2 C11.2 C12.2 C13.2 R11.1 U6.10(VDDA33) U6.15(VDD33) U6.23(VDD33) U6.29(VDDA33) U6.36(VDDA33)
+5VS: C3.2 F3.1 U5.7(IN)
GND: C3.1 C4.2 C5.2 C6.1 C7.1 C8.2 C9.1 C10.1 C11.1 C12.1 C13.1 C14.1 C15.1 C16.1 C17.1 C18.1 C69.2 J21.A4(GND2) J21.B4(GND1) J24.4 Q3.2(Y4) Q3.4(Y3) R13.1 R14.1 R15.1 R16.1 R17.1 R18.1 U5.6(GND) U6.37(Ground_Pad)
GND_SHIELD: J21.9(GND) J21.10(GND) J21.11(GND) J21.12(GND)
~{USB_HUB_A_OC}: U5.2(~{FLGA}) U6.13(OCS_N1)
~{USB_HUB_B_OC}: U5.3(~{FLGB}) U6.17(OCS_N2)
USB_HUB_A_EN: U5.1(ENA) U6.12(PRTPWR1/BC_EN1)
USB_HUB_A_N: J21.A2(~{P1}) L3.3
USB_HUB_A_P: J21.A3(P1) L3.2
USB_HUB_A_PWR: C4.1 C6.2 J21.A1(VCC2) L1.1
USB_HUB_B_EN: U5.4(ENB) U6.16(PRTPWR2/BC_EN2)
USB_HUB_B_N: J21.B2(~{P0}) L4.3
USB_HUB_B_P: J21.B3(P0) L4.2
USB_HUB_B_PWR: C5.1 C7.2 J21.B1(VCC1) L2.1
USBD_N: U6.30(USBDM_UP) ; port USB_HOST_D_N
USBD_P: U6.31(USBDP_UP) ; port USB_HOST_D_P
USBDM1_N: L3.4 U6.1(USBDM_DN1/PRT_DIS_M1)
USBDM1_P: L3.1 U6.2(USBDP_DN1/PRT_DIS_P1)
USBDM2_N: L4.4 U6.3(USBDM_DN2/PRT_DIS_M2)
USBDM2_P: L4.1 U6.4(USBDP_DN2/PRT_DIS_P2)
USBDM3_N: U6.6(USBDM_DN3/PRT_DIS_M3) ; port USB_HUB_C_N
USBDM3_P: U6.7(USBDP_DN3/PRT_DIS_P3) ; port USB_HUB_C_P
USBDM4_N: J24.2 U6.8(USBDM_DN4/PRT_DIS_M4)
USBDM4_P: J24.3 U6.9(USBDP_DN4/PRT_DIS_P4)
NetC8_1: C8.1 R11.2 U6.5(VDDA33)
NetC14_2: C14.2 C15.2 U6.14(CRFILT)
NetC16_2: C16.2 U6.34(PLLFILT)
NetC17_2: C17.2 Q3.1(Y2) R12.1 U6.33(XTALIN/CLKIN)
NetC18_2: C18.2 Q3.3(Y1) R12.2 U6.32(XTALOUT)
NetC69_1: C69.1 F3.2 J24.1
NetJ2_47: U6.27(VBUS_DET) ; port USB_HOST_PWR
NetL1_2: L1.2 U5.8(OUTA)
NetL2_2: L2.2 U5.5(OUTB)
NetQ1_3: R10.1 ; port ~{RESET_3V3}
NetR10_2: R10.2 U6.26(~{RESET})
NetR13_2: R13.2 U6.35(RBIAS)
NetR14_2: R14.2 U6.11(TEST)
NetR15_2: R15.2 U6.22(SDA/SMBDATA/NON_REM1)
NetR16_2: R16.2 U6.24(SCL/SMBCLK/CFG_SEL0)
NetR17_2: R17.2 U6.25(HS_IND/CFG_SEL1)
NetR18_2: R18.2 U6.28(SUSP_IND/LOCAL_PWR/NON_REM0)

Not connected (* = marked no-connect by the designer): U6 18(PRTPWR3/BC_EN3)* 19(OCS_N3)* 20(PRTPWR4/BC_EN4)* 21(OCS_N4)*

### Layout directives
differential pair; differential pair class USB: USB_HUB_A_N, USB_HUB_A_P, USB_HUB_B_N, USB_HUB_B_P, USBDM1_N, USBDM1_P, USBDM2_N, USBDM2_P, USBDM3_N, USBDM3_P, USBDM4_N, USBDM4_P

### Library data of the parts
C3 C6-C14 = 380: 100nF  10%  16V  X7R  0402; FS-EDV-Nummer: B.CKV.42; Class: Capacitor Ceramic; Tolerance: 10; ID: 380
C4 C5 = 719: 150uF  20%  6,3V  1411  Typ: B; FS-EDV-Nummer: B.CTA.17; Class: Capacitor Tantal; Tolerance: 20; ID: 719
C15 C16 = 394: 10uF  20%  4V  X5R  0402; FS-EDV-Nummer: B.CKV.77; Class: Capacitor Ceramic; Tolerance: 20; ID: 394
C17 C18 = 384: 22pF  5%  25V  C0G/NP0  0402; FS-EDV-Nummer: B.CKV.47; Class: Capacitor Ceramic; Tolerance: 5; ID: 384
C69 = 719: 150uF  20%  6,3V  1411  Typ: B; ID: 719; Class: Capacitor Tantal; FS-EDV-Nummer: B.CTA.17; Tolerance: 20
F3 = 2718: FUSE PTC RESETTABLE SMD 0805; ID: 2718; FS-EDV-Nummer: B.MSI.3
J21 = 2704: USB-Einbaukupplung zweifach liegend Typ A; Part Number: 2410 03; FS-EDV-Nummer: B.MBU.1R4PL.2; Class: Connector; ID: 2704; THT: X
J24 = 2807: Stiftl. 4 pol. 1 reih. RM:2,54 H=5,8mm; ID: 2807; Class: Connector; FS-EDV-Nummer: B.MST.1R4PS.2
L1 L2 = 2705: WE-CBF  25%  700R  90MHz  EMI  1206; Part Number: 74279218; FS-EDV-Nummer: B.EMVFER.5; Class: Ferit; ID: 2705
L3 L4 = 2698: Common Mode Choke  20%  2x 90 Ohm  0805; FS-EDV-Nummer: B.EMVFER.11; Power: 400mA; ID: 2698
Q3 = 2757: 24MHz 12pF 3.2x2.5 SMD; Part Number: Q22FA2380038014; ID: 2757; Class: Crystal; FS-EDV-Nummer: B.Q.28
R10 R11 = 173: 0R 1/16W max 5% SMD 0402; FS-EDV-Nummer: B.R0R0.1; Tolerance: 5; ID: 173
R12 = 180: 1M 1/16W 1% SMD 0402; FS-EDV-Nummer: B.R1M0.1; Tolerance: 1; ID: 180
R13 = 183: 12k 1/16W 1% SMD 0402; FS-EDV-Nummer: B.R12K.2; Tolerance: 1; ID: 183
R14-R18 = 170: as R3 on sheet 02) PicoCore B2B
U5 = 1285: MIC2026-1 USB Power Switch; FS-EDV-Nummer: B.ICIF.110; Class: IC; ID: 1285
U6 = 1255: USB2514B C-Temp.; ID: 1255; Class: IC; FS-EDV-Nummer: B.ICIF.80

## Sheet 04) USB AUDIO SD.SchDoc: Audio / SD-Card
size A3; Origin: Eagle; DrawnBy: T.Minas; DocumentNumber: 4; Revision: 1.50; SheetNumber: 4; SheetTotal: 10; Project: PicoCoreBBDSI
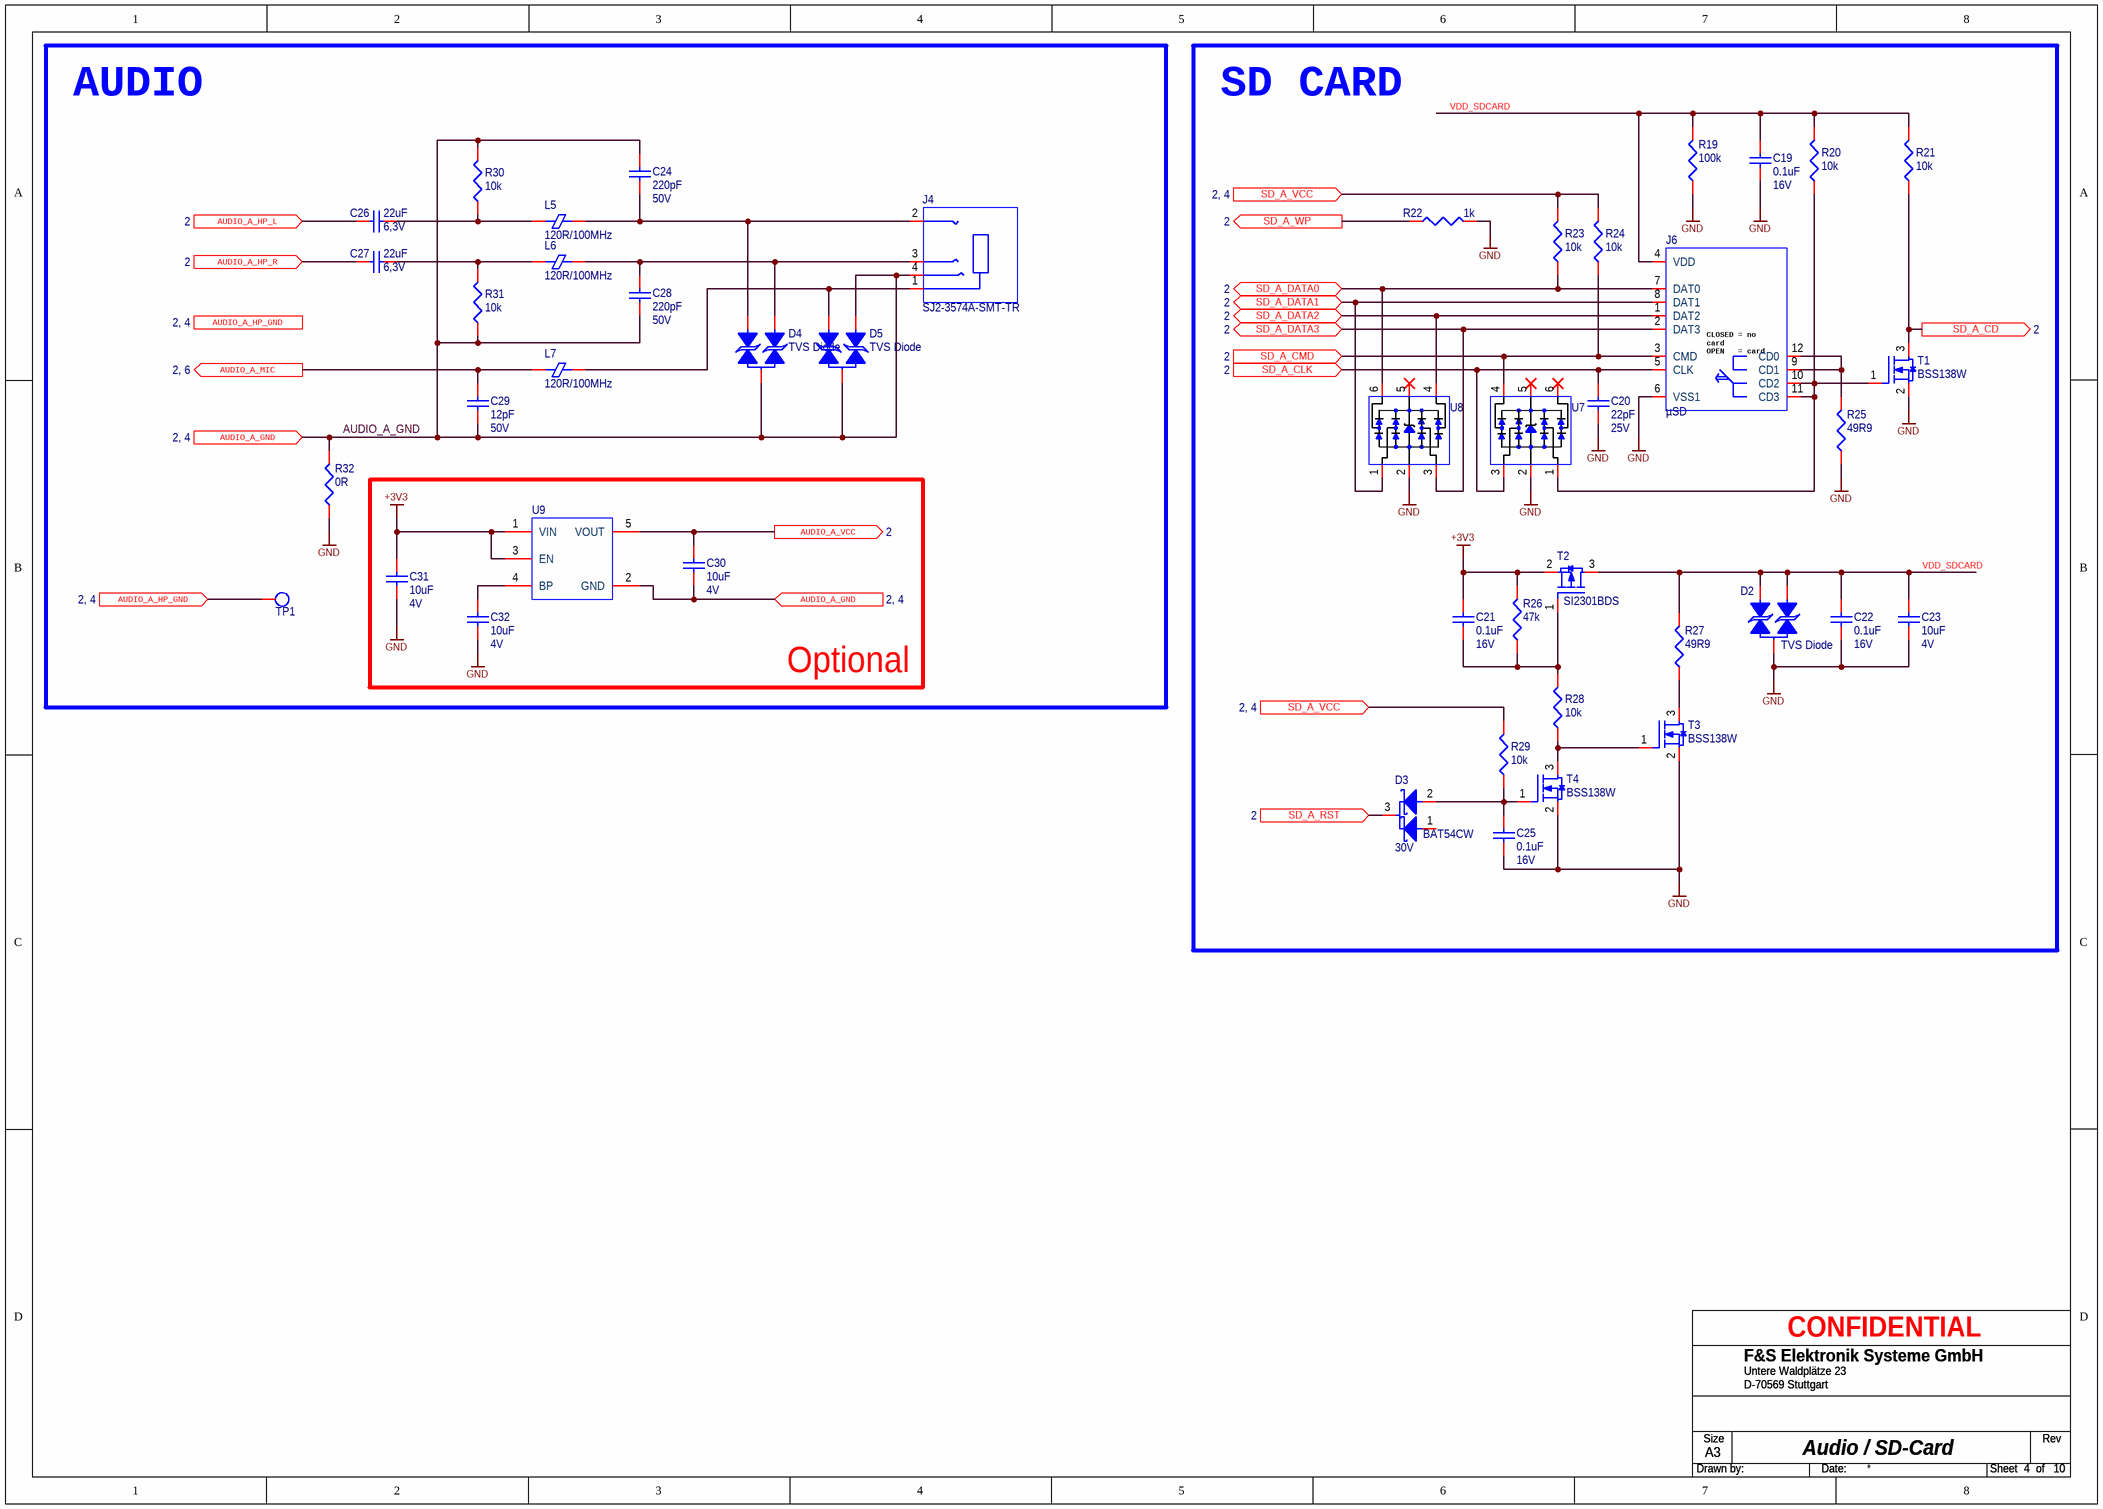
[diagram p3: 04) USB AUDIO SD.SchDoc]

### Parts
C19  0.1uF  Voltage: 16V  [C0402]
C20  22pF  Voltage: 25V  [C0402]
C21  0.1uF  Voltage: 16V  [C0402]
C22  0.1uF  Voltage: 16V  [C0402]
C23  10uF  Voltage: 4V  [C0402]
C24  220pF  Voltage: 50V  [C0402]
C25  0.1uF  Voltage: 16V  [C0402]
C26  22uF  Voltage: 6,3V  [C0603]
C27  22uF  Voltage: 6,3V  [C0603]
C28  220pF  Voltage: 50V  [C0402]
C29  12pF  Voltage: 50V  [C0402]
C30  10uF  Voltage: 4V  [C0402]
C31  10uF  Voltage: 4V  [C0402]
C32  10uF  Voltage: 4V  [C0402]
D2  TVS Diode  [SOT23-3]
D3  BAT54CW  Voltage: 30V  [SOT323 (SC70)]
D4  TVS Diode  [SOT23-3]
D5  TVS Diode  [SOT23-3]
J4  SJ2-3574A-SMT-TR  [SJ2-3574A-SMT-TR]
J6  µSD  [MicroSD_Push-Pull]
L5  120R/100MHz  [L0402]
L6  120R/100MHz  [L0402]
L7  120R/100MHz  [L0402]
R19  100k  [R0402]
R20  10k  [R0402]
R21  10k  [R0402]
R22  1k  [R0402]
R23  10k  [R0402]
R24  10k  [R0402]
R25  49R9  [R0402]
R26  47k  [R0402]
R27  49R9  [R0402]
R28  10k  [R0402]
R29  10k  [R0402]
R30  10k  [R0402]
R31  10k  [R0402]
R32  0R  [R0402]
T1  BSS138W  [SOT323 (SC70)]
T2  SI2301BDS  [SOT23-3]
T3  BSS138W  [SOT323 (SC70)]
T4  BSS138W  [SOT323 (SC70)]
TP1  TESTPOINT  [TP30SR34SMD]  (value not drawn)  (no BOM)
U7  TVS Diode  [SOT23-6]  (value not drawn)
U8  TVS Diode  [SOT23-6]  (value not drawn)
U9  (no value)  [SOT23-5]

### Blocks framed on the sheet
AUDIO: C24 C26-C29 D4 D5 J4 L5-L7 R30-R32 TP1
SD CARD: C19-C23 C25 D2 D3 J6 R19-R29 T1-T4 U7 U8
Optional: C30-C32 U9

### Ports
AUDIO_A_GND (in, see 2, 4), AUDIO_A_HP_GND (in, see 2, 4), AUDIO_A_HP_L (in, see 2), AUDIO_A_HP_R (in, see 2), AUDIO_A_MIC (out, see 2, 6), AUDIO_A_VCC (out, see 2), SD_A_CD (out, see 2), SD_A_CLK (in, see 2), SD_A_CMD (in, see 2), SD_A_DATA0 (bidir, see 2), SD_A_DATA1 (bidir, see 2), SD_A_DATA2 (bidir, see 2), SD_A_DATA3 (bidir, see 2), SD_A_RST (in, see 2), SD_A_VCC (in, see 2, 4), SD_A_WP (out, see 2)

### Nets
+3V3: C21.2 C31.2 R26.2 T2.2 U9.1(VIN) U9.3(EN)
GND: C19.1 C20.1 C22.1 C23.1 C25.1 C31.1 C32.1 D2.3 J6.6(VSS1) R19.1 R22.2 R25.1 R32.1 T1.2 T3.2 T4.2 U7.2(GND) U8.2(GND)
AUDIO_A_GND: C24.2 C28.1 C29.1 C30.1 D4.3 D5.2 D5.3 J4.4 R30.2 R31.1 R32.2 U9.2(GND) ; port AUDIO_A_GND
VDD_SDCARD: C19.2 C22.2 C23.2 D2.1 D2.2 J6.4(VDD) R19.2 R20.2 R21.2 R27.2 T2.3
NetC20_2: C20.2 J6.5(CLK) U7.3(I/O3) ; port SD_A_CLK
NetC21_1: C21.1 R26.1 R28.2 T2.1
NetC24_1: C24.1 D4.2 J4.2 L5.1(FB1)
NetC25_2: C25.2 D3.2(ANODE2) R29.1 T4.1
NetC26_1: C26.1 ; port AUDIO_A_HP_L
NetC26_2: C26.2 L5.2(FB2) R30.1
NetC27_1: C27.1 ; port AUDIO_A_HP_R
NetC27_2: C27.2 L6.2(FB2) R31.2
NetC28_2: C28.2 D4.1 J4.3 L6.1(FB1)
NetC29_2: C29.2 L7.2(FB2) ; port AUDIO_A_MIC
NetC30_2: C30.2 U9.5(VOUT) ; port AUDIO_A_VCC
NetC32_2: C32.2 U9.4(BP)
NetD3_3: D3.3(CATHODE) ; port SD_A_RST
NetD5_1: D5.1 J4.1 L7.1(FB1)
NetJ2_22: TP1.1(TP) ; port AUDIO_A_HP_GND
NetJ2_52: R23.2 R24.2 R29.2 ; port SD_A_VCC
NetJ2_58: R22.1 ; port SD_A_WP
NetJ2_60: R21.1 T1.3 ; port SD_A_CD
NetJ2_62: J6.3(CMD) R24.1 U7.4(I/O4) ; port SD_A_CMD
NetJ2_66: J6.7(DAT0) R23.1 U8.6(I/O6) ; port SD_A_DATA0
NetJ2_68: J6.8(DAT1) U8.1(I/O1) ; port SD_A_DATA1
NetJ2_70: J6.1(DAT2) U8.4(I/O4) ; port SD_A_DATA2
NetJ2_72: J6.2(DAT3) U8.3(I/O3) ; port SD_A_DATA3
NetJ6_9: J6.9(CD1) J6.12(CD0) R25.2
NetJ6_10: J6.10(CD2) J6.11(CD3) R20.1 T1.1 U7.1(I/O1)
NetR27_1: R27.1 T3.3
NetR28_1: R28.1 T3.1 T4.3

Not connected (* = marked no-connect by the designer): D3 1(ANODE1); U7 5(VCC)* 6(I/O6)*; U8 5(VCC)*

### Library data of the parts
C19 C21 C22 C25 = 380: as C3 on sheet 03) USB-HUB
C20 = 384: as C17 on sheet 03) USB-HUB
C23 C30-C32 = 394: as C15 on sheet 03) USB-HUB
C24 C28 = 374: 220pF  10%  50V  X7R  0402; FS-EDV-Nummer: B.CKV.114; Class: Capacitor Ceramic; Tolerance: 10; ID: 374
C26 C27 = 412: 22uF  20%  6,3V  X5R  0603; FS-EDV-Nummer: B.CKV.90; Class: Capacitor Ceramic; Tolerance: 0,2; ID: 412
C29 = 393: 12pF  5%  50V  C0G/NP0  0402; FS-EDV-Nummer: B.CKV.76; Class: Capacitor Ceramic; Tolerance: 5; ID: 393
D2 D4 D5 = 2709: 2 Channel ESD Protection TVS Diode SOT-23-3; Part Number: PGB102ST23WR; Number devices in Package: 1; OriginalSymbolOrigin: (0,0); FS-EDV-Nummer: B.EMVSUP.1; ID: 2709
D3 = 2695: as D1 on sheet 02) PicoCore B2B
J4 = 2711: Audio-Buchse liegend HP+MIC; ID: 2711; Class: Connector; FS-EDV-Nummer: B.MBU.AUDIO4L.1
J6 = 2712: SD-CARD Micro Steckverbinder push-pull; Part Number: 693 071 010 811; ID: 2712; Class: Connector; FS-EDV-Nummer: B.MST.1R12PL.3
L5-L7 = 2708: WE-CBF  25%  120R  100MHz  EMI  0402; Part Number: 74279271; Class: Ferit; FS-EDV-Nummer: B.EMVFER.14; ID: 2708
R19 = 177: 100k 1/16W 1% SMD 0402; FS-EDV-Nummer: B.R100K.3; Tolerance: 1; ID: 177
R20 R21 R23 R24 R28-R31 = 170: as R3 on sheet 02) PicoCore B2B
R22 = 166: 1k 1/16W 1% SMD 0402; FS-EDV-Nummer: B.R1K00.1; Tolerance: 1; ID: 166
R25 R27 = 242: 49R9 1/16W 1% SMD 0402; FS-EDV-Nummer: B.R49R9.3; Tolerance: 1; ID: 242
R26 = 186: 47k 1/16W 1% SMD 0402; FS-EDV-Nummer: B.R47K0.1; Tolerance: 1; ID: 186
R32 = 173: as R10 on sheet 03) USB-HUB
T1 T3 T4 = 2689: as Q1 on sheet 02) PicoCore B2B
T2 = 2691: Si2301BDS SOT-23 P-Kanal; FS-EDV-Nummer: B.TPMFP.2.S; Class: MOSFET; ID: 2691
U7 U8 = 2710: 4 Channel  5,5V  TVS Diode Array  SOT-23-6; Part Number: AOZ8904CIL; CLASS: ESD; FS-EDV-Nummer: B.EMVSUP.2; ID: 2710
U9 = 1748: LDO 3.3V 600mA SOT-25 SMD; Part Number: AP7365-30WG-7; FS-EDV-Nummer: B.ICANA.63; Voltage: 3.0V; Class: IC; Power: 500mA; ID: 1748

## Sheet 05) USB3.0 Type-C.SchDoc: USB3.0 Type-C
size A3; DrawnBy: T.Minas; DocumentNumber: 5; Revision: 1.50; SheetNumber: 5; SheetTotal: 10; Project: PicoCoreBBDSI
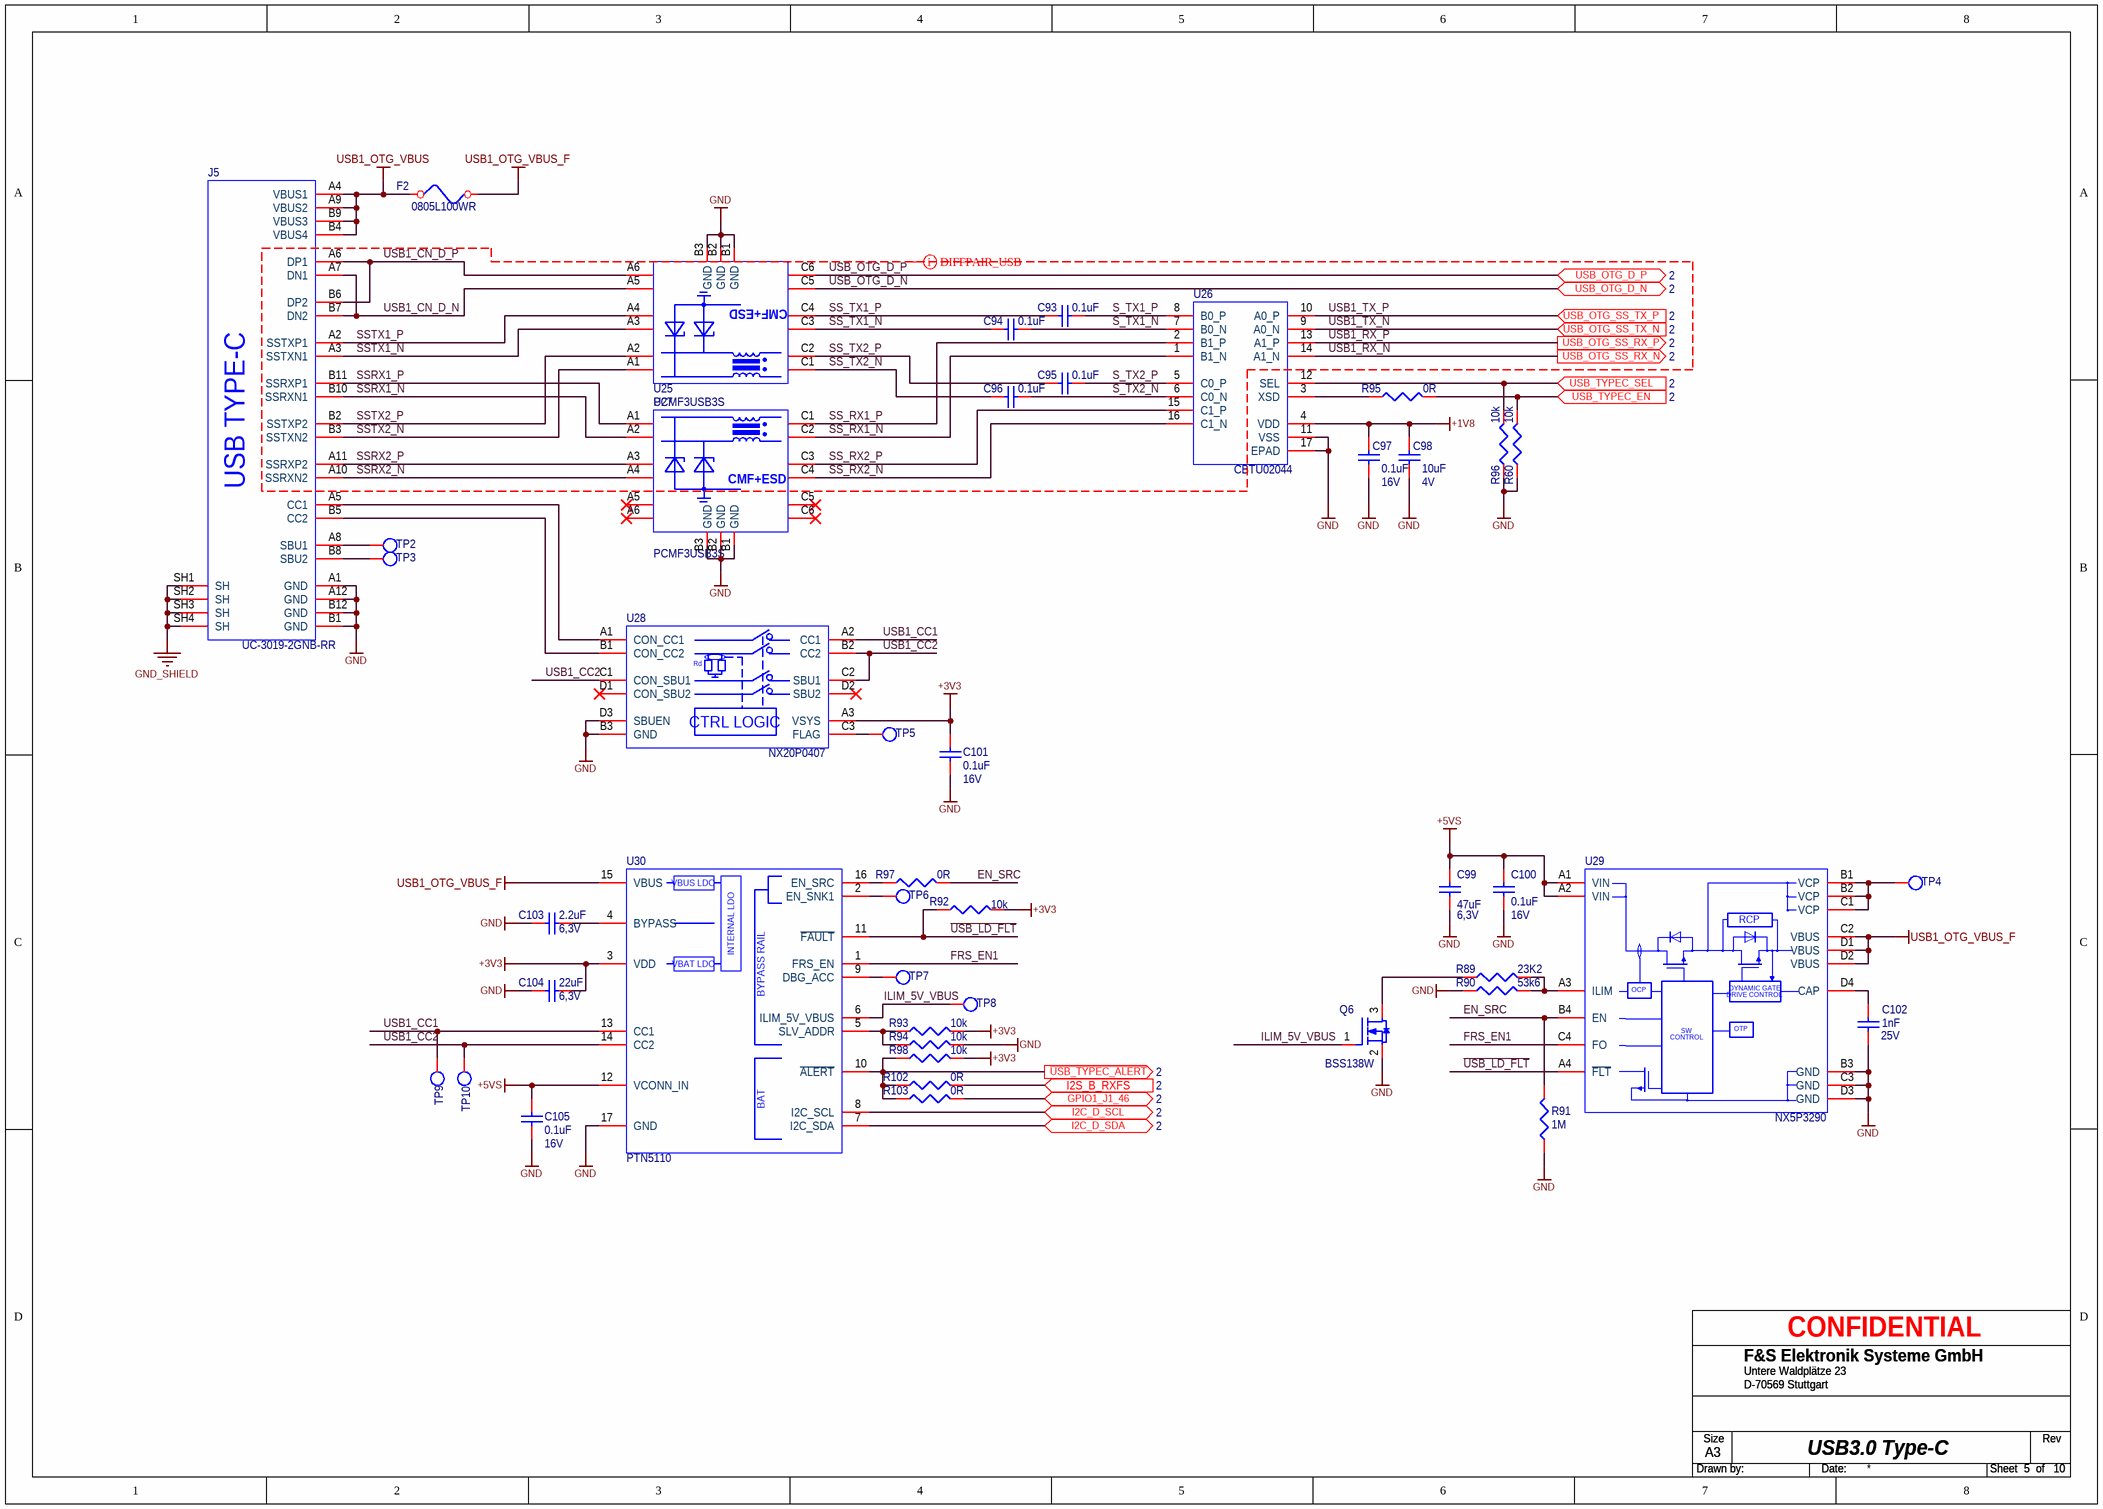
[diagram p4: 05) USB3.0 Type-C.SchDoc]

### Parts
C93  0.1uF  [C0402]
C94  0.1uF  [C0402]
C95  0.1uF  [C0402]
C96  0.1uF  [C0402]
C97  0.1uF  Voltage: 16V  [C0402]
C98  10uF  Voltage: 4V  [C0402]
C99  47uF  Voltage: 6,3V  [C0805]
C100  0.1uF  Voltage: 16V  [C0402]
C101  0.1uF  Voltage: 16V  [C0402]
C102  1nF  Voltage: 25V  [C0402]
C103  2.2uF  Voltage: 6,3V  [C0402]
C104  22uF  Voltage: 6,3V  [C0603]
C105  0.1uF  Voltage: 16V  [C0402]
F2  0805L100WR  [FUSE0805]
J5  UC-3019-2GNB-RR  [UC-3019-2GNB-RR]
Q6  BSS138W  [SOT323 (SC70)]
R60  10k  [R0402]
R89  23K2  [R0402]
R90  53k6  [R0402]
R91  1M  [R0402]
R92  10k  [R0402]
R93  10k  [R0402]
R94  10k  [R0402]
R95  0R  [R0402]
R96  10k  [R0402]
R97  0R  [R0402]
R98  10k  [R0402]
R102  0R  [R0402]
R103  0R  [R0402]
TP2  TESTPOINT  [TP30SR34SMD]  (value not drawn)  (no BOM)
TP3  TESTPOINT  [TP30SR34SMD]  (value not drawn)  (no BOM)
TP4  TESTPOINT  [TP30SR34SMD]  (value not drawn)  (no BOM)
TP5  TESTPOINT  [TP30SR34SMD]  (value not drawn)  (no BOM)
TP6  TESTPOINT  [TP30SR34SMD]  (value not drawn)  (no BOM)
TP7  TESTPOINT  [TP30SR34SMD]  (value not drawn)  (no BOM)
TP8  TESTPOINT  [TP30SR34SMD]  (value not drawn)  (no BOM)
TP9  TESTPOINT  [TP30SR34SMD]  (value not drawn)  (no BOM)
TP10  TESTPOINT  [TP30SR34SMD]  (value not drawn)  (no BOM)
U25  PCMF3USB3S  [WLCSP15]
U26  CBTU02044  [HUQFN16]
U27  PCMF3USB3S  [WLCSP15]
U28  NX20P0407  [WLCSP12]
U29  NX5P3290  [WLCSP16]
U30  PTN5110  [HX2QFN16]

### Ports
GPIO1_J1_46 (bidir, see 2), I2C_D_SCL (bidir, see 2), I2C_D_SDA (bidir, see 2), I2S_B_RXFS (in, see 2), USB_OTG_D_N (bidir, see 2), USB_OTG_D_P (bidir, see 2), USB_OTG_SS_RX_N (out, see 2), USB_OTG_SS_RX_P (out, see 2), USB_OTG_SS_TX_N (in, see 2), USB_OTG_SS_TX_P (in, see 2), USB_TYPEC_EN (in, see 2), USB_TYPEC_SEL (in, see 2), ~{USB_TYPEC_ALERT} (out, see 2)

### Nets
+1V8: C97.2 C98.2 U26.4(VDD)
+3V3: C101.2 C104.2 R92.2 R93.2 R98.2 U28.A3(VSYS) U30.3(VDD)
+5VS: C99.2 C100.2 C105.2 U29.A1(VIN) U29.A2(VIN) U30.12(VCONN_IN)
GND: C97.1 C98.1 C99.1 C100.1 C101.1 C102.2 C103.1 C104.1 C105.1 J5.A1(GND) J5.A12(GND) J5.B1(GND) J5.B12(GND) Q6.2 R60.1 R90.1 R91.1 R94.2 R96.1 U25.B1(GND) U25.B2(GND) U25.B3(GND) U26.11(VSS) U26.17(EPAD) U27.B1(GND) U27.B2(GND) U27.B3(GND) U28.B3(GND) U28.D3(SBUEN) U29.B3(GND) U29.C3(GND) U29.D3(GND) U30.17(GND)
GND_SHIELD: J5.SH1(SH) J5.SH2(SH) J5.SH3(SH) J5.SH4(SH)
USB1_OTG_VBUS: F2.1 J5.A4(VBUS1) J5.A9(VBUS2) J5.B4(VBUS4) J5.B9(VBUS3)
USB1_OTG_VBUS_F: F2.2 U29.C2(VBUS) U29.D1(VBUS) U29.D2(VBUS) U30.15(VBUS)
~{USB_LD_FLT}: R92.1 U29.A4(~{FLT}) U30.11(~{FAULT})
EN_SRC: R91.2 R97.2 U29.B4(EN)
FRS_EN1: U29.C4(FO) U30.1(FRS_EN)
GPIO_J1_46: R103.2 ; port GPIO1_J1_46
I2S_B_RXFS: R102.2 ; port I2S_B_RXFS
ILIM_5V_VBUS: Q6.1 TP8.1(TP) U30.6(ILIM_5V_VBUS)
S_TX1_N: C94.2 U26.7(B0_N)
S_TX1_P: C93.2 U26.8(B0_P)
S_TX2_N: C96.2 U26.6(C0_N)
S_TX2_P: C95.2 U26.5(C0_P)
SS_RX1_N: U26.1(B1_N) U27.C2
SS_RX1_P: U26.2(B1_P) U27.C1
SS_RX2_N: U26.16(C1_N) U27.C4
SS_RX2_P: U26.15(C1_P) U27.C3
SS_TX1_N: C94.1 U25.C3
SS_TX1_P: C93.1 U25.C4
SS_TX2_N: C96.1 U25.C1
SS_TX2_P: C95.1 U25.C2
SSRX1_N: J5.B10(SSRXN1) U27.A2
SSRX1_P: J5.B11(SSRXP1) U27.A1
SSRX2_N: J5.A10(SSRXN2) U27.A4
SSRX2_P: J5.A11(SSRXP2) U27.A3
SSTX1_N: J5.A3(SSTXN1) U25.A3
SSTX1_P: J5.A2(SSTXP1) U25.A4
SSTX2_N: J5.B3(SSTXN2) U25.A1
SSTX2_P: J5.B2(SSTXP2) U25.A2
USB1_CC1: TP9.1(TP) U28.A2(CC1) U30.13(CC1)
USB1_CC2: TP10.1(TP) U28.B2(CC2) U28.C1(CON_SBU1) U28.C2(SBU1) U30.14(CC2)
USB1_CN_D_N: J5.A7(DN1) J5.B7(DN2) U25.A5
USB1_CN_D_P: J5.A6(DP1) J5.B6(DP2) U25.A6
USB1_RX_N: U26.14(A1_N) ; port USB_OTG_SS_RX_N
USB1_RX_P: U26.13(A1_P) ; port USB_OTG_SS_RX_P
USB1_TX_N: U26.9(A0_N) ; port USB_OTG_SS_TX_N
USB1_TX_P: U26.10(A0_P) ; port USB_OTG_SS_TX_P
USB_OTG_D_N: U25.C5 ; port USB_OTG_D_N
USB_OTG_D_P: U25.C6 ; port USB_OTG_D_P
NetC102_1: C102.1 U29.D4(CAP)
NetC103_2: C103.2 U30.4(BYPASS)
NetJ1_48: U30.8(I2C_SCL) ; port I2C_D_SCL
NetJ1_50: U30.7(I2C_SDA) ; port I2C_D_SDA
NetJ3_13: R60.2 R95.2 ; port USB_TYPEC_EN
NetJ3_15: R98.1 R102.1 R103.1 U30.10(~{ALERT}) ; port ~{USB_TYPEC_ALERT}
NetJ3_17: R96.2 U26.12(SEL) ; port USB_TYPEC_SEL
NetJ5_A5: J5.A5(CC1) U28.A1(CON_CC1)
NetJ5_A8: J5.A8(SBU1) TP2.1(TP)
NetJ5_B5: J5.B5(CC2) U28.B1(CON_CC2)
NetJ5_B8: J5.B8(SBU2) TP3.1(TP)
NetQ6_3: Q6.3 R89.1
NetR89_2: R89.2 R90.2 U29.A3(ILIM)
NetR93_1: R93.1 R94.1 U30.5(SLV_ADDR)
NetR95_1: R95.1 U26.3(XSD)
NetR97_1: R97.1 U30.16(EN_SRC)
NetTP4_1: TP4.1(TP) U29.B1(VCP) U29.B2(VCP) U29.C1(VCP)
NetTP5_1: TP5.1(TP) U28.C3(FLAG)
NetTP6_1: TP6.1(TP) U30.2(EN_SNK1)
NetTP7_1: TP7.1(TP) U30.9(DBG_ACC)

Not connected (* = marked no-connect by the designer): U27 A5* A6* C5* C6*; U28 D1(CON_SBU2)* D2(SBU2)*

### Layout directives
differential pair; differential pair class USB: +1V8, S_TX1_N, S_TX1_P, S_TX2_N, S_TX2_P, SS_RX1_N, SS_RX1_P, SS_RX2_N, SS_RX2_P, SS_TX1_N, SS_TX1_P, SS_TX2_N, SS_TX2_P, SSRX1_N, SSRX1_P, SSRX2_N, SSRX2_P, SSTX1_N, SSTX1_P, SSTX2_N, SSTX2_P, USB1_CN_D_N, USB1_CN_D_P, USB1_RX_N, USB1_RX_P, USB1_TX_N, USB1_TX_P, USB_OTG_D_N, USB_OTG_D_P

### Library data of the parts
C93-C96 = 380: 100nF  10%  16V  X7R  0402; ID: 380; Class: Capacitor Ceramic; FS-EDV-Nummer: B.CKV.42; Tolerance: 10
C97 C100 C101 C105 = 380: as C3 on sheet 03) USB-HUB
C98 = 394: as C15 on sheet 03) USB-HUB
C99 = 442: 47uF  20%  6,3V  X5R  0805; ID: 442; Class: Capacitor Ceramic; FS-EDV-Nummer: B.CKV.69; Tolerance: 20
C102 = 381: 1nF  10%  25V  X7R  0402; ID: 381; Class: Capacitor Ceramic; FS-EDV-Nummer: B.CKV.43; Tolerance: 10
C103 = 392: 2,2uF  20%  6,3V  X5R  0402; Part Number: 2,2uF; ID: 392; Class: Capacitor Ceramic; FS-EDV-Nummer: B.CKV.75; Tolerance: 20
C104 = 412: 22uF  20%  6,3V  X5R  0603; ID: 412; Class: Capacitor Ceramic; FS-EDV-Nummer: B.CKV.90; Tolerance: 0,2
F2 = 2718: as F3 on sheet 03) USB-HUB
J5 = 2784: USB Typ C Buchse liegend SMD; ID: 2784; Class: Connector; FS-EDV-Nummer: B.MBU.2R24PL.5
Q6 = 2689: BSS138W SOT323(SC-70) N-Kanal; ID: 2689; Class: MOSFET; FS-EDV-Nummer: B.TPMFN.10
R60 R92-R94 R96 R98 = 170: 10k 1/16W 1% SMD 0402; ID: 170; FS-EDV-Nummer: B.R10K.3; Tolerance: 1
R89 = 337: 23K2 / 1/16W / 1% / SMD / 0402; ID: 337; FS-EDV-Nummer: B.R23K2.1; Tolerance: 1
R90 = 273: 53k6 1/16W 1% SMD 0402; ID: 273; FS-EDV-Nummer: B.R53K6.1; Tolerance: 1
R91 = 180: 1M 1/16W 1% SMD 0402; ID: 180; FS-EDV-Nummer: B.R1M0.1; Tolerance: 1
R95 R97 R102 R103 = 173: 0R 1/16W max 5% SMD 0402; ID: 173; FS-EDV-Nummer: B.R0R0.1; Tolerance: 5
U25 U27 = 2765: USB3.0 EMI filter & ESD Protection; Voltage: -0.5...5V; ID: 2765; Class: EMI ESD; FS-EDV-Nummer: B.ICIF.156
U26 = 2766: High-speed differential 1-to-2 switch; Part Number: CBTU02044HEJ; Voltage: 1.62...3.63V; ID: 2766; Class: IC; FS-EDV-Nummer: B.ICIF.179
U28 = 2767: USB Type-C CC and SBU Protection IC; Part Number: NX20P0407UK; Voltage: -0.5...6V; ID: 2767; FS-EDV-Nummer: B.ICIF.178
U29 = 1328: USB PD and Type-C current-limited power switch; ID: 1328; Class: IC; FS-EDV-Nummer: B.ICIF.153
U30 = 2770: USB PD TCPC PHY IC; Voltage: 2.7...5.5V; ID: 2770; FS-EDV-Nummer: B.ICIF.152

## Sheet 06) Serial GPIO.SchDoc: Serial / GPIO / SPI
size A3; Origin: Eagle; DrawnBy: T.Minas; DocumentNumber: 6; Revision: 1.50; SheetNumber: 6; SheetTotal: 10; Project: PicoCoreBBDSI
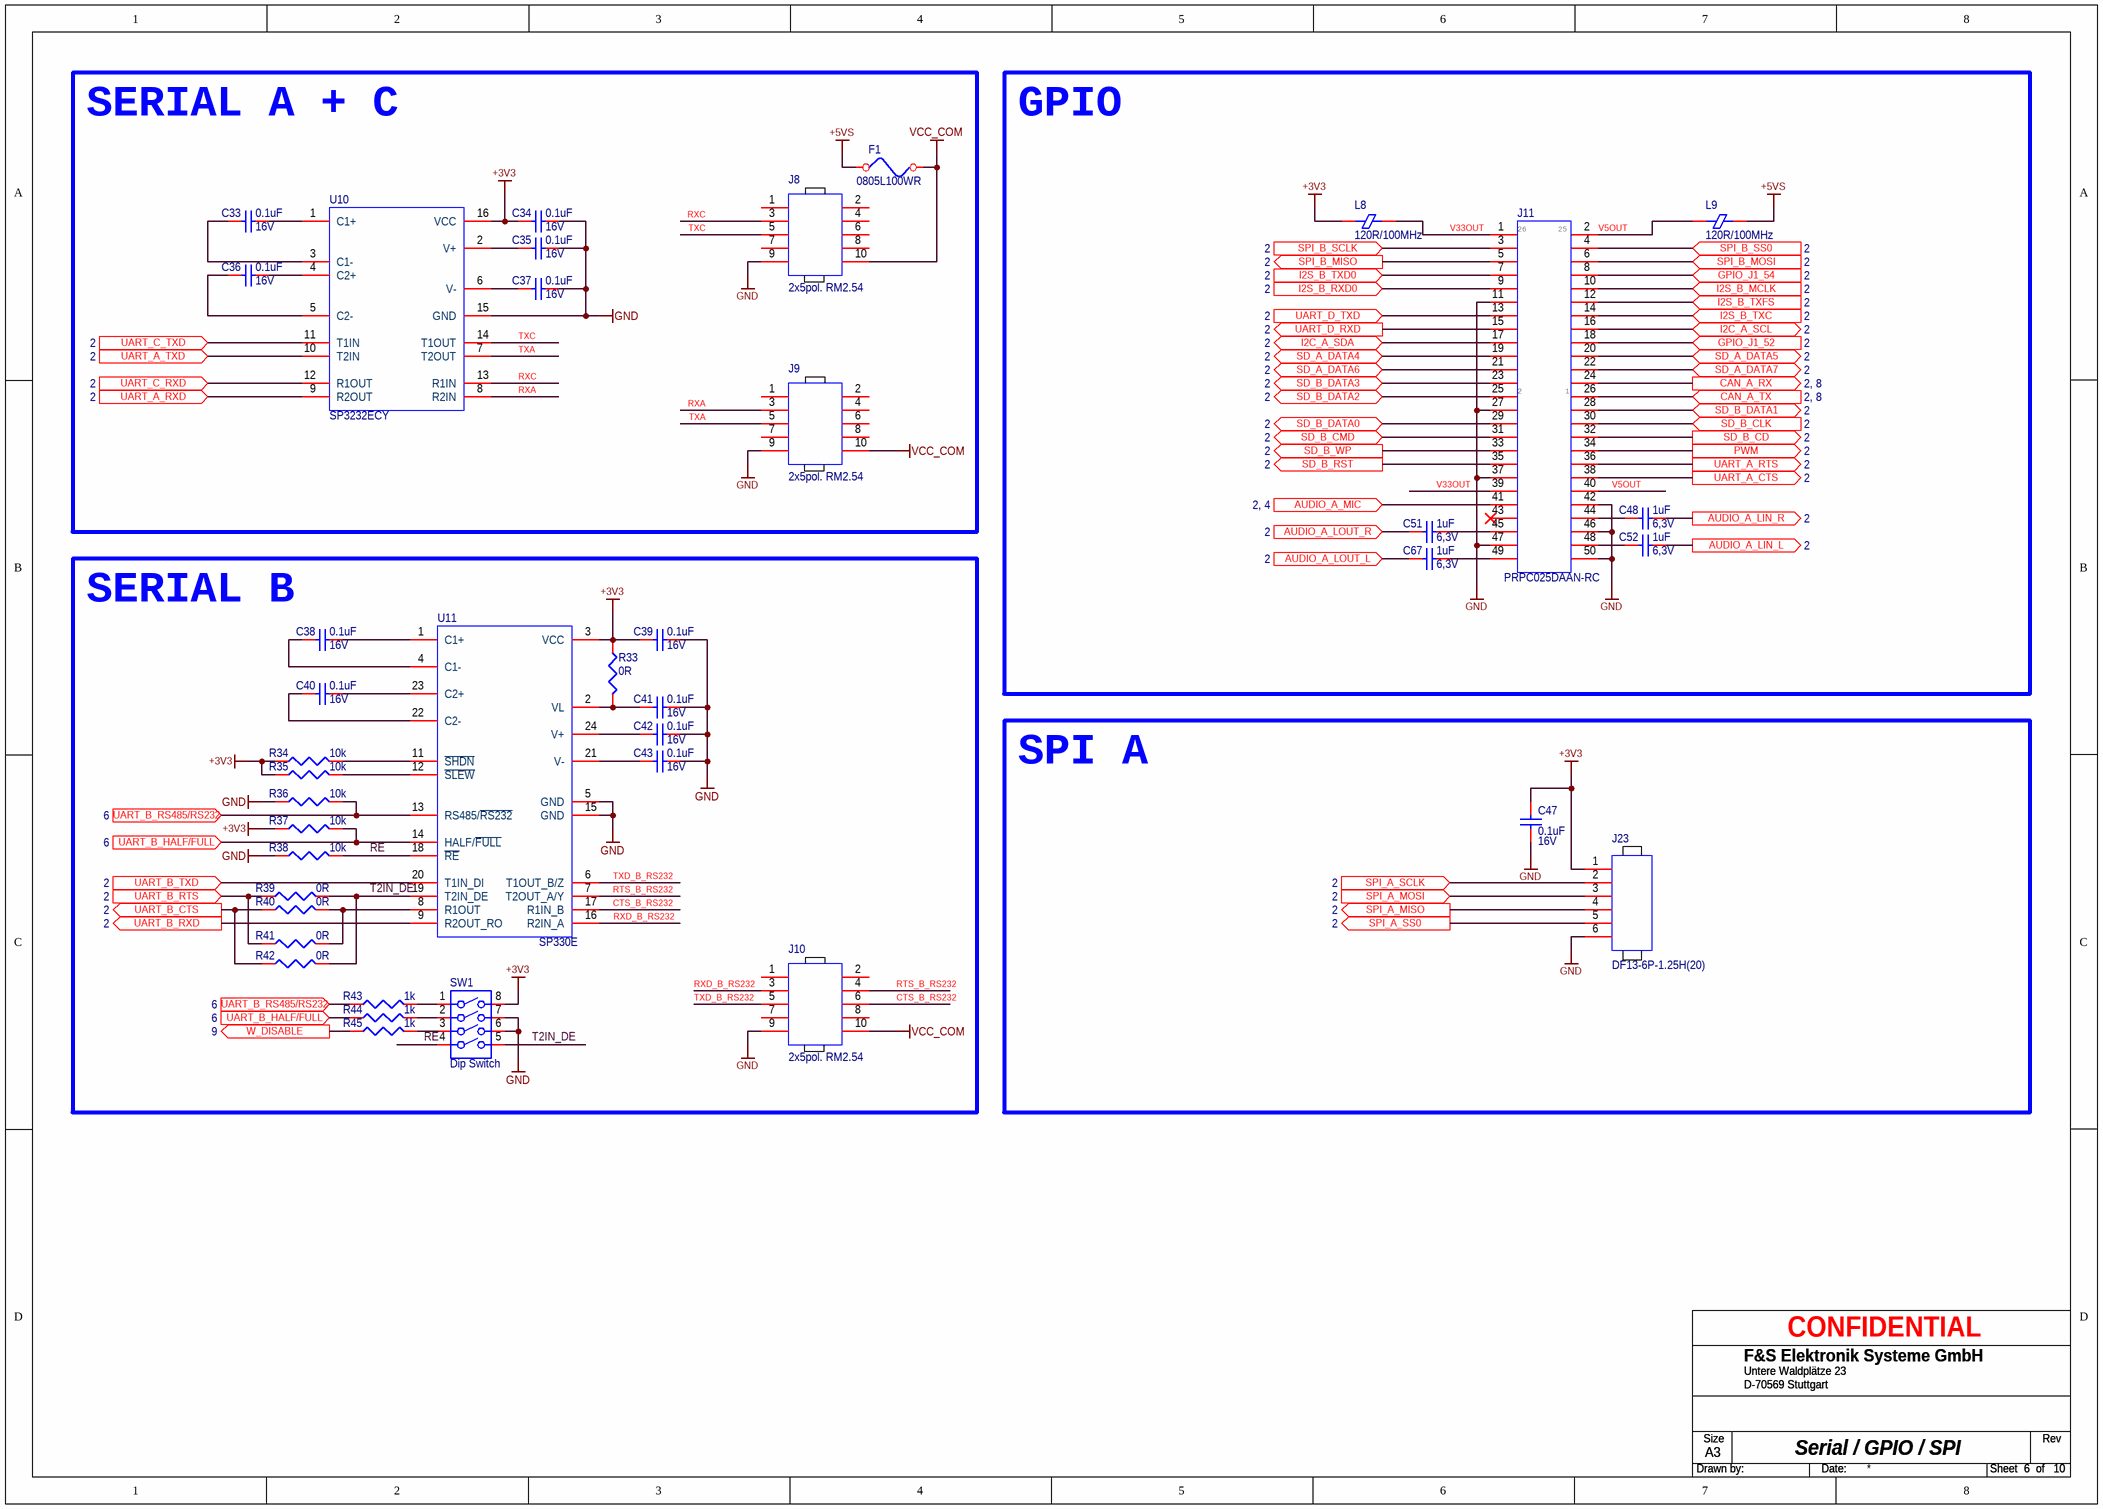
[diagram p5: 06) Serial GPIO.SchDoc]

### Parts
C33  0.1uF  Voltage: 16V  [C0402]
C34  0.1uF  Voltage: 16V  [C0402]
C35  0.1uF  Voltage: 16V  [C0402]
C36  0.1uF  Voltage: 16V  [C0402]
C37  0.1uF  Voltage: 16V  [C0402]
C38  0.1uF  Voltage: 16V  [C0402]
C39  0.1uF  Voltage: 16V  [C0402]
C40  0.1uF  Voltage: 16V  [C0402]
C41  0.1uF  Voltage: 16V  [C0402]
C42  0.1uF  Voltage: 16V  [C0402]
C43  0.1uF  Voltage: 16V  [C0402]
C47  0.1uF  Voltage: 16V  [C0402]
C48  1uF  Voltage: 6,3V  [C0402]
C51  1uF  Voltage: 6,3V  [C0402]
C52  1uF  Voltage: 6,3V  [C0402]
C67  1uF  Voltage: 6,3V  [C0402]
F1  0805L100WR  [FUSE0805]
J8  2x5pol. RM2.54  [COM-5X2]
J9  2x5pol. RM2.54  [COM-5X2]
J10  2x5pol. RM2.54  [COM-5X2]
J11  PRPC025DAAN-RC  [COM-25X2]
J23  DF13-6P-1.25H(20)  [DF13-6P-1.25H(20)]
L8  120R/100MHz  [L0603]
L9  120R/100MHz  [L0603]
R33  0R  [R0402]
R34  10k  [R0402]
R35  10k  [R0402]
R36  10k  [R0402]
R37  10k  [R0402]
R38  10k  [R0402]
R39  0R  [R0402]
R40  0R  [R0402]
R41  0R  [R0402]
R42  0R  [R0402]
R43  1k  [R0402]
R44  1k  [R0402]
R45  1k  [R0402]
SW1  Dip Switch  [MCDM(R)-04-T]
U10  SP3232ECY  [TSSOP16-065M]
U11  SP330E  [TSSOP24_065P]

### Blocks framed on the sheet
SERIAL A + C: C33-C37 F1 J8 J9 U10
GPIO: C48 C51 C52 C67 J11 L8 L9
SERIAL B: C38-C43 J10 R33-R45 SW1 U11
SPI A: C47 J23

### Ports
AUDIO_A_LIN_L (out, see 2), AUDIO_A_LIN_R (out, see 2), AUDIO_A_LOUT_L (in, see 2), AUDIO_A_LOUT_R (in, see 2), AUDIO_A_MIC (in, see 2, 4), CAN_A_RX (out, see 2, 8), CAN_A_TX (in, see 2, 8), GPIO_J1_52 (in, see 2), GPIO_J1_54 (in, see 2), I2C_A_SCL (bidir, see 2), I2C_A_SDA (bidir, see 2), I2S_B_MCLK (in, see 2), I2S_B_RXD0 (in, see 2), I2S_B_TXC (in, see 2), I2S_B_TXD0 (in, see 2), I2S_B_TXFS (in, see 2), PWM (out, see 2), SD_A_DATA4 (bidir, see 2), SD_A_DATA5 (bidir, see 2), SD_A_DATA6 (bidir, see 2), SD_A_DATA7 (bidir, see 2), SD_B_CD (out, see 2), SD_B_CLK (in, see 2), SD_B_CMD (bidir, see 2), SD_B_DATA0 (bidir, see 2), SD_B_DATA1 (bidir, see 2), SD_B_DATA2 (bidir, see 2), SD_B_DATA3 (bidir, see 2), SD_B_RST (out, see 2), SD_B_WP (out, see 2), SPI_A_MISO (out, see 2), SPI_A_MOSI (in, see 2), SPI_A_SCLK (in, see 2), SPI_A_SS0 (out, see 2), SPI_B_MISO (out, see 2), SPI_B_MOSI (in, see 2), SPI_B_SCLK (in, see 2), SPI_B_SS0 (in, see 2), UART_A_CTS (out, see 2), UART_A_RTS (out, see 2), UART_A_RXD (in, see 2), UART_A_TXD (in, see 2), UART_B_CTS (out, see 2), UART_B_HALF/FULL (in, see 6), UART_B_RS485/RS232 (in, see 6), UART_B_RTS (in, see 2), UART_B_RXD (out, see 2), UART_B_TXD (in, see 2), UART_C_RXD (in, see 2), UART_C_TXD (in, see 2), UART_D_RXD (out, see 2), UART_D_TXD (in, see 2), W_DISABLE (out, see 9)

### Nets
+3V3: C34.1 C39.1 C47.2 J23.1 L8.2(FB2) R33.1 R34.1 R35.1 R37.1 SW1.8 U10.16(VCC) U11.3(VCC)
+5VS: F1.1 L9.1(FB1)
GND: C34.2 C35.2 C37.2 C39.2 C41.2 C42.2 C43.2 C47.1 J8.9 J9.9 J10.9 J11.11 J11.27 J11.37 J11.42 J11.46 J11.47 J11.50 J23.6 R36.1 R38.1 SW1.6 SW1.7 U10.15(GND) U11.5(GND) U11.15(GND)
VCC_COM: F1.2 J8.10 J9.10 J10.10
~{RE}: R38.2 SW1.4 U11.18(~{RE})
CTS_B_RS232: J10.6 U11.17(R1IN_B)
RTS_B_RS232: J10.4 U11.7(T2OUT_A/Y)
RXA: J9.3 U10.8(R2IN)
RXC: J8.3 U10.13(R1IN)
RXD_B_RS232: J10.3 U11.16(R2IN_A)
T2IN_DE: R39.2 R42.2 SW1.5 U11.19(T2IN_DE)
TXA: J9.5 U10.7(T2OUT)
TXC: J8.5 U10.14(T1OUT)
TXD_B_RS232: J10.5 U11.6(T1OUT_B/Z)
V5OUT: J11.2 J11.40 L9.2(FB2)
V33OUT: J11.1 J11.39 L8.1(FB1)
NetC29_2: J11.41 ; port AUDIO_A_MIC
NetC33_1: C33.1 U10.3(C1-)
NetC33_2: C33.2 U10.1(C1+)
NetC35_1: C35.1 U10.2(V+)
NetC36_1: C36.1 U10.5(C2-)
NetC36_2: C36.2 U10.4(C2+)
NetC37_1: C37.1 U10.6(V-)
NetC38_1: C38.1 U11.4(C1-)
NetC38_2: C38.2 U11.1(C1+)
NetC40_1: C40.1 U11.22(C2-)
NetC40_2: C40.2 U11.23(C2+)
NetC41_1: C41.1 R33.2 U11.2(VL)
NetC42_1: C42.1 U11.24(V+)
NetC43_1: C43.1 U11.21(V-)
NetC48_1: C48.1 J11.44
NetC48_2: C48.2 ; port AUDIO_A_LIN_R
NetC51_1: C51.1 ; port AUDIO_A_LOUT_R
NetC51_2: C51.2 J11.45
NetC52_1: C52.1 J11.48
NetC52_2: C52.2 ; port AUDIO_A_LIN_L
NetC67_1: C67.1 ; port AUDIO_A_LOUT_L
NetC67_2: C67.2 J11.49
NetJ1_4: J11.16 ; port I2C_A_SCL
NetJ1_6: J11.17 ; port I2C_A_SDA
NetJ1_10: J11.24 ; port CAN_A_RX
NetJ1_12: J11.26 ; port CAN_A_TX
NetJ1_14: J11.36 ; port UART_A_RTS
NetJ1_16: J11.38 ; port UART_A_CTS
NetJ1_18: U10.9(R2OUT) ; port UART_A_RXD
NetJ1_20: U10.10(T2IN) ; port UART_A_TXD
NetJ1_22: R39.1 R41.1 ; port UART_B_RTS
NetJ1_24: R40.1 R42.1 ; port UART_B_CTS
NetJ1_26: U11.9(R2OUT_RO) ; port UART_B_RXD
NetJ1_28: U11.20(T1IN_DI) ; port UART_B_TXD
NetJ1_30: U10.12(R1OUT) ; port UART_C_RXD
NetJ1_32: U10.11(T1IN) ; port UART_C_TXD
NetJ1_34: J11.15 ; port UART_D_RXD
NetJ1_36: J11.13 ; port UART_D_TXD
NetJ1_52: J11.18 ; port GPIO_J1_52
NetJ1_54: J11.8 ; port GPIO_J1_54
NetJ1_56: J11.4 ; port SPI_B_SS0
NetJ1_58: J11.5 ; port SPI_B_MISO
NetJ1_60: J11.6 ; port SPI_B_MOSI
NetJ1_62: J11.3 ; port SPI_B_SCLK
NetJ1_64: J23.5 ; port SPI_A_SS0
NetJ1_66: J23.4 ; port SPI_A_MISO
NetJ1_68: J23.3 ; port SPI_A_MOSI
NetJ1_70: J23.2 ; port SPI_A_SCLK
NetJ2_63: J11.34 ; port PWM
NetJ2_65: J11.10 ; port I2S_B_MCLK
NetJ2_67: J11.12 ; port I2S_B_TXFS
NetJ2_69: J11.14 ; port I2S_B_TXC
NetJ2_73: J11.7 ; port I2S_B_TXD0
NetJ2_74: J11.19 ; port SD_A_DATA4
NetJ2_75: J11.9 ; port I2S_B_RXD0
NetJ2_76: J11.20 ; port SD_A_DATA5
NetJ2_78: J11.21 ; port SD_A_DATA6
NetJ2_80: J11.22 ; port SD_A_DATA7
NetJ2_84: J11.35 ; port SD_B_RST
NetJ2_86: J11.33 ; port SD_B_WP
NetJ2_88: J11.32 ; port SD_B_CD
NetJ2_90: J11.31 ; port SD_B_CMD
NetJ2_92: J11.30 ; port SD_B_CLK
NetJ2_94: J11.29 ; port SD_B_DATA0
NetJ2_96: J11.28 ; port SD_B_DATA1
NetJ2_98: J11.25 ; port SD_B_DATA2
NetJ2_100: J11.23 ; port SD_B_DATA3
NetJ18_20: R45.1 ; port W_DISABLE
NetR34_2: R34.2 U11.11(~{SHDN})
NetR35_2: R35.2 U11.12(~{SLEW})
NetR36_2: R36.2 R43.1 U11.13(RS485/~{RS232}) ; port UART_B_RS485/RS232
NetR37_2: R37.2 R44.1 U11.14(HALF/~{FULL}) ; port UART_B_HALF/FULL
NetR40_2: R40.2 R41.2 U11.8(R1OUT)
NetR43_2: R43.2 SW1.1
NetR44_2: R44.2 SW1.2
NetR45_2: R45.2 SW1.3

Not connected (* = marked no-connect by the designer): J8 1 2 4 6 7 8; J9 1 2 4 6 7 8; J10 1 2 7 8; J11 43*

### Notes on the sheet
- (near J11) 26
- (near J11) 25
- (near J11) 2
- (near J11) 1

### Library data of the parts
C33-C43 = 380: as C3 on sheet 03) USB-HUB
C47 = 380: as C93 on sheet 05) USB3.0 Type-C
C48 C51 C52 C67 = 383: 1uF  20%  6,3V  X5R/X7R  0402; ID: 383; Class: Capacitor Ceramic; FS-EDV-Nummer: B.CKV.45; Tolerance: 20
F1 = 2718: FUSE PTC RESETTABLE SMD 0805; FS-EDV-Nummer: B.MSI.3; ID: 2718
J8-J10 = 2714: Stiftl. mit Wanne 10 pol. 2 reih.  steh.; FS-EDV-Nummer: B.MST.2R10PS.4; Class: Connector; ID: 2714; THT: X
J11 = 2717: Stiftl. 50 pol. 2 reih. RM2,54 H=5,8mm; FS-EDV-Nummer: B.MST.2R50PS.3; Class: Connector; ID: 2717; THT: X
J23 = 2720: Stiftl. 6 pol. crimpable  liegend RM:1.25; FS-EDV-Nummer: B.MST.1R6PL.2; Class: Connector; ID: 2720
L8 L9 = 2707: Ferritperlen  25%  120R  100MHz  0603; Part Number: 74279262; Class: Ferit; FS-EDV-Nummer: B.EMVFER.9; ID: 2707
R33 = 173: as R10 on sheet 03) USB-HUB
R34-R38 = 170: as R3 on sheet 02) PicoCore B2B
R39-R42 = 173: as R95 on sheet 05) USB3.0 Type-C
R43-R45 = 166: as R22 on sheet 04) USB AUDIO SD
SW1 = 2756: Kodierschalter 4 pol. SMD; ID: 2756; FS-EDV-Nummer: B.SW.4X1A1.2
U10 = 1210: SP3232ECY SMD TSSOP16  C-Temp.; FS-EDV-Nummer: B.ICIF.40; Voltage: 3...5,5V; Class: IC; ID: 1210
U11 = 2755: SP330E / TSSOP24 / SMD / RS-232/RS-485 Transceiver; Part Number: SP330EEY-L/TR; Voltage: 3...5.5V; ID: 2755; Class: IC; FS-EDV-Nummer: B.ICIF.169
